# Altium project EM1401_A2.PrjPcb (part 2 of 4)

## Sheet BOTTOM_ACB_Converter.SchDoc: Bottom Tigon (PWM controller)
size B; Date: Not shown in title block; ApprovedBy: Not shown in title block; CheckedBy: Not shown in title block; Author: Not shown in title block; CompanyName: Not shown in title block; DrawnBy: Not shown in title block; Engineer: Not shown in title block; Organization: Not shown in title block; Address1: Not shown in title block; Address2: Not shown in title block; Address3: Not shown in title block; Address4: Not shown in title block; DocumentNumber: 6; Revision: Use project parameter SCH_Rev; SheetNumber: 7; SheetTotal: 14; PageSetup: Record=PageOptions|CenterHorizontal=True|CenterVertical=True|PrintScale=1.09|XCorrection=1.00|YCorrection=1.00|PrintKind=0|BorderSize=5000000|LeftOffset=0|BottomOffset=0|Orientation=2|PaperLength=1000|PaperWidth=1000|Scale=100|PaperSource=15|PrintQuality=600|MediaType=1|DitherType=10|PaperKind=11x17|PrintScaleMode=1
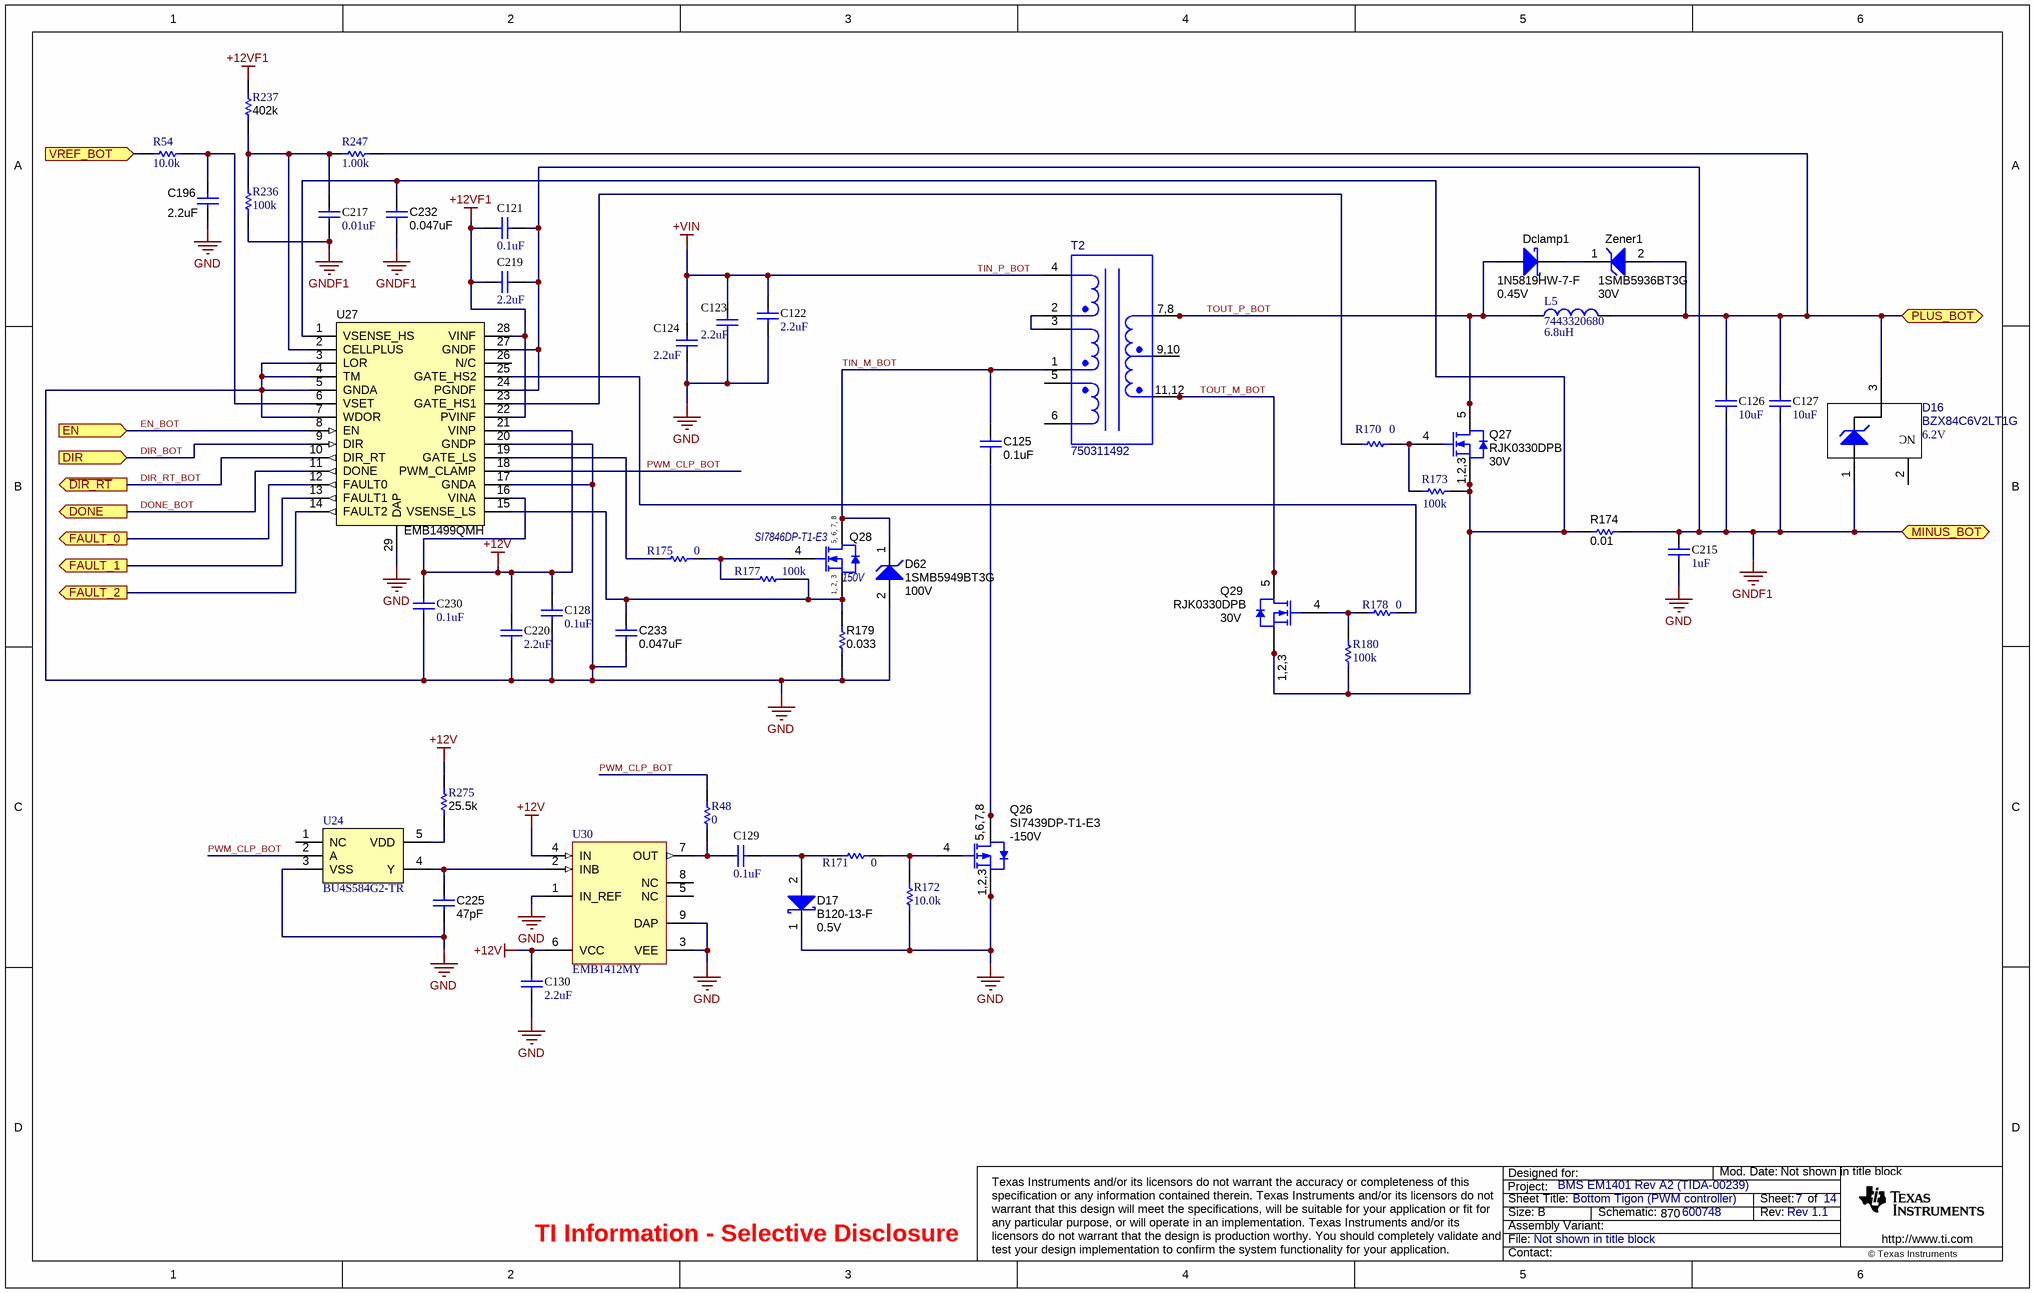
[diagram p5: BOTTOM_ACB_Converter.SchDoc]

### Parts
C121  value 0.1uF  [0603L]  (hidden comment: C1608X7R1C104K)
C122  value 2.2uF  [1210L]  (hidden comment: GRM32ER72A225KA35L)
C123  value 2.2uF  [1210L]  (hidden comment: GRM32ER72A225KA35L)
C124  value 2.2uF  [1210L]  (hidden comment: GRM32ER72A225KA35L)
C125  value 0.1uF  [1206L]  (hidden comment: 12061C104KAT2A)
C126  value 10uF  [1206L]  (hidden comment: GRM319R61A106KE19D)
C127  value 10uF  [1206L]  (hidden comment: GRM319R61A106KE19D)
C128  value 0.1uF  [0603L]  (hidden comment: C1608X7R1C104K)
C129  value 0.1uF  [0603L]  (hidden comment: C1608X7R1C104K)
C130  value 2.2uF  [0805_HV]  (hidden comment: C0805C225K4RACTU)
C196  value 2.2uF  [0603L]  (hidden comment: C1608X5R0J225M)
C215  value 1uF  [1210L]  (hidden comment: GRM32ER72A105KA01L)
C217  value 0.01uF  [0603L]  (hidden comment: GRM188R71C103KA01D)
C219  value 2.2uF  [0805_HV]  (hidden comment: C0805C225K4RACTU)
C220  value 2.2uF  [0805_HV]  (hidden comment: C0805C225K4RACTU)
C225  value 47pF  [0603L]  (hidden comment: 06035A470JAT2A)
C230  value 0.1uF  [0603L]  (hidden comment: C1608X7R1C104K)
C232  value 0.047uF  [0603L]  (hidden comment: C1608X7R1E473K)
C233  value 0.047uF  [0603L]  (hidden comment: C1608X7R1E473K)
D16  BZX84C6V2LT1G  value 6.2V  [MF03A_L]
D17  B120-13-F  value 0.5V  [SMA]
D62  1SMB5949BT3G  value 100V  [SMB]
Dclamp1  1N5819HW-7-F  value 0.45V  [SOD-123]
L5  7443320680  Ind_H: 6.8uH  [Wurth 7443320680]
Q26  SI7439DP-T1-E3  value -150V  [PowerPAK_SO-8]
Q27  RJK0330DPB  value 30V  [LFPAK]
Q28  SI7846DP-T1-E3  value 150V  [PowerPAK_SO-8]
Q29  RJK0330DPB  value 30V  [LFPAK]
R48  value 0  [0603L]  (hidden comment: CRCW06030000Z0EA)
R54  value 10.0k  [0603L]  (hidden comment: RT0603BRD0710KL)
R170  value 0  [0603L]  (hidden comment: CRCW06030000Z0EA)
R171  value 0  [0603L]  (hidden comment: CRCW06030000Z0EA)
R172  value 10.0k  [0603L]  (hidden comment: RT0603BRD0710KL)
R173  value 100k  [0603L]  (hidden comment: CRCW0603100KFKEA)
R174  value 0.01  [2010M]  (hidden comment: WSL2010R0100FEA18)
R175  value 0  [0603L]  (hidden comment: CRCW06030000Z0EA)
R177  value 100k  [0603L]  (hidden comment: CRCW0603100KFKEA)
R178  value 0  [0603L]  (hidden comment: CRCW06030000Z0EA)
R179  value 0.033  [1812]  (hidden comment: ERJ-L12KF33MU)
R180  value 100k  [0603L]  (hidden comment: CRCW0603100KFKEA)
R236  value 100k  [0603L]  (hidden comment: CRCW0603100KFKEA)
R237  value 402k  [0603L]  (hidden comment: RC0603FR-07402KL)
R247  value 1.00k  [0603L]  (hidden comment: CRCW06031K00FKEA)
R275  value 25.5k  [0603L]  (hidden comment: CRCW060325K5FKEA)
T2  750311492  [WE EFD20-SMD Transformer]
U24  BU4S584G2-TR  [MF05A_M]
U27  EMB1499QMH  [MXA28A_M]
U30  EMB1412MY  [MUY08A_N]
Zener1  1SMB5936BT3G  value 30V  [SMB]

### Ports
DIR (in), DONE (out), EN (in), FAULT_0 (out), FAULT_1 (out), FAULT_2 (out), MINUS_BOT (bidir), PLUS_BOT (bidir), VREF_BOT (in), ~{DIR_RT} (out)

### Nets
+12V: C128.2 C130.1 C220.1 C230.2 R275.2 U27.16(VINA) U27.21(VINP) U30.4(IN) U30.6(VCC)
+12VF1: C121.1 C219.1 R237.2 U27.22(PVINF) U27.28(VINF)
GND: C122.2 C123.2 C124.2 C128.1 C130.2 C196.2 C215.2 C220.2 C225.2 C230.1 C233.2 D17.1(K) D62.2(A) Q26.1(S) Q26.2(S) Q26.3(S) R172.2 R179.1 U24.3(VSS) U27.3(LOR) U27.4(TM) U27.5(GNDA) U27.7(WDOR) U27.17(GNDA) U27.20(GNDP) U27.29(DAP) U30.1(IN_REF) U30.3(VEE) U30.9(DAP)  [project net BAT0]
GNDF1: C121.2 C126.2 C127.2 C215.1 C217.2 C219.2 C232.1 D16.1(A) R174.2 R236.2 U27.24(PGNDF) U27.27(GNDF) ; port MINUS_BOT
TIN_P_BOT: C122.1 C123.1 C124.1 T2.4  [also labelled +VIN]
DIR_BOT: U27.9(DIR) ; port DIR
DIR_RT_BOT: U27.10(DIR_RT) ; port ~{DIR_RT}
DONE_BOT: U27.11(DONE) ; port DONE
EN_BOT: U27.8(EN) ; port EN
PWM_CLP_BOT: R48.1 U24.2(A) U27.18(PWM_CLAMP)
TIN_M_BOT: C125.1 D62.1(K) Q28.5(D) Q28.6(D) Q28.7(D) Q28.8(D) T2.1
TOUT_M_BOT: Q29.5(D) Q29.6(D) T2.11 T2.12
TOUT_P_BOT: Dclamp1.2(A) L5.1 Q27.5(D) Q27.6(D) T2.7 T2.8
VREF_BOT_: R54.2 ; port VREF_BOT
NetC125_2: C125.2 Q26.5(D) Q26.6(D) Q26.7(D) Q26.8(D) Q26.9(D)
NetC126_1: C126.1 C127.1 D16.3(K) L5.2 R247.1 Zener1.2(A) ; port PLUS_BOT
NetC129_1: C129.1 D17.2(A) R171.2
NetC129_2: C129.2 R48.2 U30.7(OUT)
NetC196_1: C196.1 R54.1 U27.6(VSET)
NetC217_1: C217.1 R236.1 R237.1 R247.2 U27.2(CELLPLUS)
NetC225_1: C225.1 U24.4(Y) U30.2(INB)
NetC232_2: C232.2 Q27.1(S) Q27.2(S) Q27.3(S) Q29.1(S) Q29.2(S) Q29.3(S) R173.1 R174.1 R180.2 U27.1(VSENSE_HS)
NetC233_1: C233.1 Q28.1(S) Q28.2(S) Q28.3(S) R177.1 R179.2 U27.15(VSENSE_LS)
NetDclamp1_1: Dclamp1.1(K) Zener1.1(K)
NetQ26_4: Q26.4(G) R171.1 R172.1
NetQ27_4: Q27.4(G) R170.1 R173.2
NetQ28_4: Q28.4(G) R175.1 R177.2
NetQ29_4: Q29.4(G) R178.2 R180.1
NetR170_2: R170.2 U27.23(GATE_HS1)
NetR175_2: R175.2 U27.19(GATE_LS)
NetR178_1: R178.1 U27.25(GATE_HS2)
NetR275_1: R275.1 U24.5(VDD)
NetT2_2: T2.2 T2.3
NetT2_9: T2.9 T2.10
NetU6_20: U27.14(FAULT2) ; port FAULT_2
NetU6_21: U27.13(FAULT1) ; port FAULT_1
NetU6_22: U27.12(FAULT0) ; port FAULT_0

Not connected (* = marked no-connect by the designer): D16 2(NC); T2 5 6; U24 1(NC); U27 26(N/C); U30 5(NC) 8(NC)

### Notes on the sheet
- TI Information - Selective Disclosure

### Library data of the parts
C121 C128 C129 C230 = C1608X7R1C104K: CAP, CERM, 0.1uF, 16V, +/-10%, X7R, 0603; Manufacturer: TDK; Cap_Case: 0603; ESR_Ohm: 0.017; Polarized: N; TaMax_C: 125; TaMin_C: -55; Tolerance_%: 10; VDC_V: 16; Cap_F: 0.0000001; CompType: Capacitor; Value1: 0.017 ohm; U/M: EA; ValueDisplayed: 0.1µF
C122-C124 = GRM32ER72A225KA35L: CAP, CERM, 2.2uF, 100V, +/-10%, X7R, 1210; Manufacturer: MuRata; Cap_Case: 1210; ESR_Ohm: 0.007; IRMS_A: 4.4; Polarized: N; TaMax_C: 125; TaMin_C: -55; Tolerance_%: 10; VDC_V: 100; Cap_F: 0.0000022; CompType: Capacitor; Value1: 0.007 ohm; U/M: EA; ValueDisplayed: 2.2µF
C125 = 12061C104KAT2A: CAP, CERM, 0.1uF, 100V, +/-10%, X7R, 1206; Manufacturer: AVX; Cap_Case: 1206; ESR_Ohm: 0.037; Polarized: N; TaMax_C: 125; TaMin_C: -55; Tolerance_%: 10; VDC_V: 100; Cap_F: 0.0000001; CompType: Capacitor; Value1: 0.037 ohm; U/M: EA; ValueDisplayed: 0.1µF
C126 C127 = GRM319R61A106KE19D: CAP, CERM, 10uF, 10V, +/-10%, X5R, 1206; Manufacturer: MuRata; Cap_Case: 1206; ESR_Ohm: 0.004; Polarized: N; TaMax_C: 85; TaMin_C: -55; Tolerance_%: 10; Cap_F: 0.00001; CompType: Capacitor; Value1: 0.004 ohm; U/M: EA; ValueDisplayed: 10µF
C130 C219 C220 = C0805C225K4RACTU: CAP, CERM, 2.2uF, 16V, +/-10%, X7R, 0805; Manufacturer: Kemet; Cap_Case: 0805; ESR_Ohm: 0.008; IRMS_A: 15.55; Polarized: N; TaMax_C: 125; TaMin_C: -55; Tolerance_%: 10; VDC_V: 16; Cap_F: 0.0000022; CompType: Capacitor; Value1: 0.008 ohm; U/M: EA; ValueDisplayed: 2.2µF
C196 = C1608X5R0J225M: CAP, CERM, 2.2uF, 6.3V, +/-20%, X5R, 0603; Manufacturer: TDK; Cap_Case: 0603; ESR_Ohm: 0.004; Polarized: N; TaMax_C: 85; TaMin_C: -55; Tolerance_%: 20; VDC_V: 6.3; Cap_F: 0.0000022; CompType: Capacitor; Value1: 0.004 ohm; U/M: EA; ValueDisplayed: 2.2µF
C215 = GRM32ER72A105KA01L: CAP, CERM, 1uF, 100V, +/-10%, X7R, 1210; Manufacturer: MuRata; Cap_Case: 1210; Polarized: N; TaMax_C: 125; TaMin_C: -55; Tolerance_%: 10; VDC_V: 100; Cap_F: 0.000001; CompType: Capacitor; U/M: EA; ValueDisplayed: 1µF
C217 = GRM188R71C103KA01D: CAP, CERM, 0.01uF, 16V, +/-10%, X7R, 0603; Manufacturer: MuRata; Cap_Case: 0603; Polarized: N; TaMax_C: 125; TaMin_C: -55; Tolerance_%: 10; VDC_V: 16; Cap_F: 0.00000001; CompType: Capacitor; U/M: EA; ValueDisplayed: 0.01µF
C225 = 06035A470JAT2A: CAP, CERM, 47pF, 50V, +/-5%, C0G/NP0, 0603; Manufacturer: AVX; Cap_Case: 0603; ESR_Ohm: 0.174; Polarized: N; TaMax_C: 125; TaMin_C: -55; Tolerance_%: 5; VDC_V: 50; Cap_F: 0.000000000047; CompType: Capacitor; Value1: 0.174 ohm; U/M: EA
C232 C233 = C1608X7R1E473K: CAP, CERM, 0.047uF, 25V, +/-10%, X7R, 0603; Manufacturer: TDK; Cap_Case: 0603; ESR_Ohm: 0.0234; Polarized: N; TaMax_C: 125; TaMin_C: -55; Tolerance_%: 10; VDC_V: 25; Cap_F: 0.000000047; CompType: Capacitor; Value1: 0.0234 ohm; U/M: EA; ValueDisplayed: 0.047µF
D16 = BZX84C6V2LT1G: SMT Zener Diode; Manufacturer: ON Semiconductor; Power_W: 0.225; Vz: 6.2; Value1: 0.225V; RJA_CperW: 556
D17 = B120-13-F: Diode, Schottky, 20V, 1A, SMA; Manufacturer: Diodes Inc.; RJC_CperW: 20; Vf_V: 0.5; Io_A: 1; TJMax_C: 150; U/M: EA
D62 = 1SMB5949BT3G: Diode, Zener, 100V, 550mW, SMB; Manufacturer: ON Semiconductor; U/M: EA; Power_W: 0.55; Vz: 100; Value1: 0.55W; RJA_CperW: 226
Dclamp1 = 1N5819HW-7-F: Diode, Schottky, 40V, 1A, SOD-123; Manufacturer: Diodes Inc.; Vf_V: 0.45; Io_A: 1; Vr_V: 40; TJMax_C: 125; U/M: EA
L5 = 7443320680: Wurth 6.8uH Power Inductor; Manufacturer: Wurth Elektronik; DCR_Ohm: 8.98; Value1: 13A
Q26 = SI7439DP-T1-E3: MOSFET, P-CH, -150V, -3A, PowerPAK SO-8; Manufacturer: Vishay-Siliconix; ChType: P; VdsMax_V: -150; Value1: ? ohm; Value2: 88 nC; QgTyp_nC: 88; Vgs_V: -20; IdsMax_A: -3; U/M: EA
Q27 Q29 = RJK0330DPB: 45A, 27nC, rDS(on) @ 4.5V =0.0028 ohm; Manufacturer: Renesas; CompType: MOSFET; ChType: N; VdsMax_V: 30; Rdson45_Ohm: 0.0028; QgTyp_nC: 27; Vgs_V: 20; IdsMax_A: 45
Q28 = BSC014N03LS G: 100A, 47nC, rDS(on) @ 4.5V =0.0021 Ohm; Manufacturer: Vishay/Siliconix; DesignatorOriginal: Q1-tw; A_Properties: MOSFET N-CH 150V 4A PPAK 8SOIC; Type: N-CH FET; Value1: 50mOhm; Value2: 30nC
R48 R170 R171 R175 R178 = CRCW06030000Z0EA: RES, 0 ohm, 5%, 0.1W, 0603; Manufacturer: Vishay-Dale; CompType: Resistor; Tolerance_%: 5; VDC_V: 75; Power_W: 0.1; Value_Code: 0000; EIA_Code: E24; TempCo: 200 ppm/C; U/M: EA
R54 R172 = RT0603BRD0710KL: RES, 10.0k ohm, 0.1%, 0.1W, 0603; Manufacturer: Yageo America; CompType: Resistor; Tolerance_%: 0.1; VDC_V: 75; Res_Ohm: 10000; Value_Code: 10k0; EIA_Code: E192; TempCo: 25 ppm/C; U/M: EA
R173 R177 R180 R236 = CRCW0603100kFKEA: RES, 100k ohm, 1%, 0.1W, 0603; Manufacturer: Vishay-Dale; CompType: Resistor; Tolerance_%: 1; VDC_V: 75; Power_W: 0.1; Res_Ohm: 100000; EIA_Code: E96; TempCo: 100 ppm/C; U/M: EA
R174 = WSL2010R0100FEA18: RES, 0.01 ohm, 1%, 1W, 2010; Manufacturer: Vishay-Dale; CompType: Resistor; Tolerance_%: 1; Value_Code: R010; EIA_Code: E96; TempCo: 75 ppm/C; U/M: EA
R179 = ERJ-L12KF33MU: RES, 0.033 ohm, 1%, 0.5W, 1812; Manufacturer: Panasonic; CompType: Resistor; Tolerance_%: 1; Power_W: 0.5; Value_Code: R033; EIA_Code: E96; TempCo: 300 ppm/C; U/M: EA
R237 = RC0603FR-07402KL: RES, 402k ohm, 1%, 0.1W, 0603; Manufacturer: Yageo America; CompType: Resistor; Tolerance_%: 1; VDC_V: 150; Power_W: 0.1; Res_ohm: 402000; EIA_Code: E96; U/M: EA; TempCo: 200 ppm/C
R247 = CRCW06031k00FKEA: RES, 1.00k ohm, 1%, 0.1W, 0603; Manufacturer: Vishay-Dale; CompType: Resistor; Tolerance_%: 1; VDC_V: 75; Power_W: 0.1; Res_Ohm: 1000; Value_Code: 1k00; EIA_Code: E96; TempCo: 100 ppm/C; U/M: EA
R275 = CRCW060325K5FKEA: RES, 25.5k ohm, 1%, 0.1W, 0603; Manufacturer: Vishay-Dale; CompType: Resistor; Tolerance_%: 1; VDC_V: 75; Power_W: 0.1; Res_Ohm: 25500; Value_Code: 25k5; EIA_Code: E96; TempCo: 100 ppm/C; U/M: EA
T2 = EFD20-SMD: Forward Transformer; Manufacturer: Wurth Elektronik; SymbolVersion: use current date i.e. 2008-05-20; SymbolCreator: Use LDAP id
U24 = BU4S584G2-TR: IC INVERTER WITH SCHMITT TRIGGER SINGLE; Manufacturer: Rohm Semiconductor; Res_Ohm: 200000; Value1: 3V-16V; Value2: 3.4mA Drive
U27 = EMB1499QMH: PWM Controller; Manufacturer: National Semiconductor; CompType: Used in BOM report; SymbolVersion: use current date i.e. 2008-05-20; SymbolCreator: Use LDAP id
U30 = EMB1412MY: Dual 5A Compound Gate Driver; Manufacturer: National Semiconductor; CompType: Switcher; PowerWise: N
Zener1 = 1SMB5936BT3G: Diode, Zener, 30V, 550mW, SMB; Manufacturer: ON Semiconductor; U/M: EA; Power_W: 0.55; Vz: 30; Value1: 0.55W; RJA_CperW: 226

## Sheet VR.SchDoc: VR (Power Supplies)
size B; Date: Not shown in title block; ApprovedBy: Not shown in title block; CheckedBy: Not shown in title block; Author: Not shown in title block; CompanyName: Not shown in title block; DrawnBy: Not shown in title block; Engineer: Not shown in title block; Organization: Not shown in title block; Address1: Not shown in title block; Address2: Not shown in title block; Address3: Not shown in title block; Address4: Not shown in title block; DocumentNumber: 15; Revision: Use project parameter SCH_Rev; SheetNumber: 13; SheetTotal: 14; PageSetup: Record=PageOptions|CenterHorizontal=True|CenterVertical=True|PrintScale=0.70|XCorrection=1.00|YCorrection=1.00|PrintKind=0|BorderSize=5000000|LeftOffset=0|BottomOffset=0|Orientation=2|PaperLength=1000|PaperWidth=1000|Scale=100|PaperSource=268|PrintQuality=-3|MediaType=1|DitherType=10|PaperKind=Letter 8.5"x11"|PrintScaleMode=1
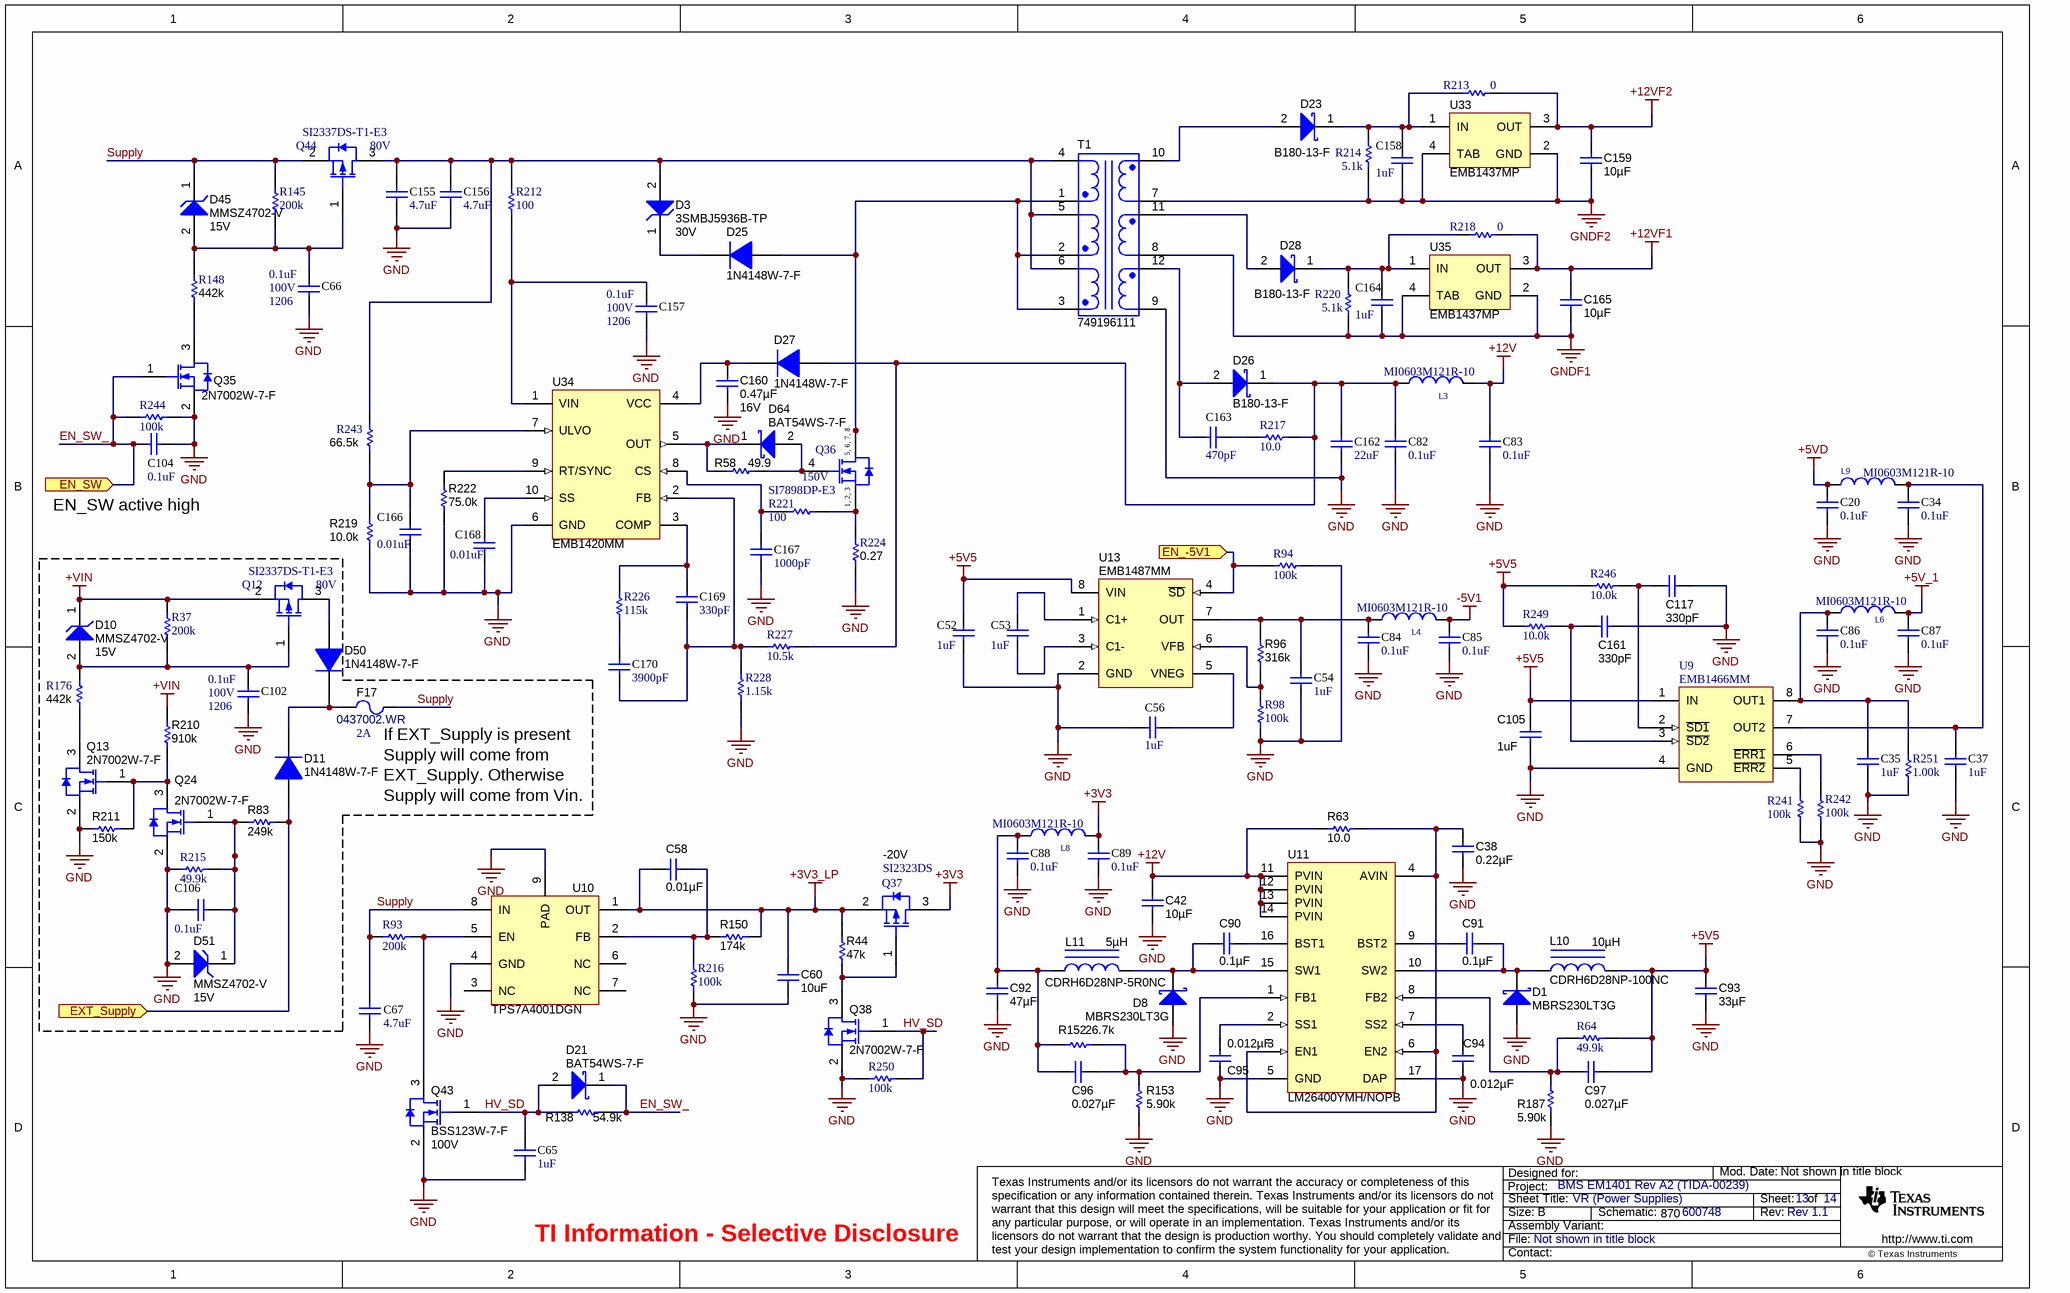
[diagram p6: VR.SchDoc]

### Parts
C20  value 0.1uF  [0603L]  (hidden comment: C1608X7R1C104K)
C34  value 0.1uF  [0603L]  (hidden comment: C1608X7R1C104K)
C35  value 1uF  [0805_HV]  (hidden comment: C2012X7R1E105K)
C37  value 1uF  [0805_HV]  (hidden comment: C2012X7R1E105K)
C38  ValueDisplayed: 0.22µF  [0603L]  (hidden comment: C1608X7R1C224K)
C42  ValueDisplayed: 10µF  [1210]  (hidden comment: GRM32DR61E106KA12L)
C52  value 1uF  [0805_HV]  (hidden comment: C2012X7R1E105K)
C53  value 1uF  [0805_HV]  (hidden comment: C2012X7R1E105K)
C54  value 1uF  [0805_HV]  (hidden comment: C2012X7R1E105K)
C56  value 1uF  [0805_HV]  (hidden comment: C2012X7R1E105K)
C58  ValueDisplayed: 0.01µF  [0805_HV]  (hidden comment: GRM21BR72A103KA01L)
C60  value 10uF  [1206L]  (hidden comment: C3216X7R1C106M)
C65  value 1uF  [0805_HV]  (hidden comment: C2012X7R1E105K)
C66  value 0.1uF  PackageReference: 1206  Value2: 100V  [1206L]  (hidden comment: C3216X7R2A104K)
C67  value 4.7uF  [1210L]  (hidden comment: GRM32ER71H475KA88L)
C82  value 0.1uF  [0603L]  (hidden comment: C1608X7R1C104K)
C83  value 0.1uF  [0603L]  (hidden comment: C1608X7R1C104K)
C84  value 0.1uF  [0603L]  (hidden comment: C1608X7R1C104K)
C85  value 0.1uF  [0603L]  (hidden comment: C1608X7R1C104K)
C86  value 0.1uF  [0603L]  (hidden comment: C1608X7R1C104K)
C87  value 0.1uF  [0603L]  (hidden comment: C1608X7R1C104K)
C88  value 0.1uF  [0603L]  (hidden comment: C1608X7R1C104K)
C89  value 0.1uF  [0603L]  (hidden comment: C1608X7R1C104K)
C90  ValueDisplayed: 0.1µF  [0603L]  (hidden comment: C1608X7R1C104K)
C91  ValueDisplayed: 0.1µF  [0603L]  (hidden comment: C1608X7R1C104K)
C92  ValueDisplayed: 47µF  [0805_HV]  (hidden comment: JMK212BJ476MG-T)
C93  ValueDisplayed: 33µF  [1210]  (hidden comment: GRM32DR60J336ME19L)
C94  ValueDisplayed: 0.012µF  [0603L]  (hidden comment: GRM188R71C123KA01D)
C95  ValueDisplayed: 0.012µF  [0603L]  (hidden comment: GRM188R71C123KA01D)
C96  ValueDisplayed: 0.027µF  [0603L]  (hidden comment: GRM188R71E273KA01D)
C97  ValueDisplayed: 0.027µF  [0603L]  (hidden comment: GRM188R71E273KA01D)
C102  value 0.1uF  PackageReference: 1206  Value2: 100V  [1206L]  (hidden comment: C3216X7R2A104K)
C104  value 0.1uF  [0603L]  (hidden comment: C1608X7R1C104K)
C105  value 1uF  [0603L]  (hidden comment: C1608X7R1C105K)
C106  value 0.1uF  [0603L]  (hidden comment: C1608X7R1C104K)
C117  ValueDisplayed: 330pF  [0603L]  (hidden comment: C0603C331K5RACTU)
C155  value 4.7uF  [1210L]  (hidden comment: GRM32ER71H475KA88L)
C156  value 4.7uF  [1210L]  (hidden comment: GRM32ER71H475KA88L)
C157  value 0.1uF  PackageReference: 1206  Value2: 100V  [1206L]  (hidden comment: C3216X7R2A104K)
C158  value 1uF  [0805_HV]  (hidden comment: C2012X7R1E105K)
C159  ValueDisplayed: 10µF  [1210]  (hidden comment: C3225X7R1C106M)
C160  ValueDisplayed: 0.47µF  Value2: 16V  [0603]  (hidden comment: GRM188R61C474KA93D)
C161  ValueDisplayed: 330pF  [0603L]  (hidden comment: C0603C331K5RACTU)
C162  value 22uF  [1210L]  (hidden comment: C3225X5R1C226M)
C163  value 470pF  [0805_HV]  (hidden comment: CC0805JRNP09BN471)
C164  value 1uF  [0805_HV]  (hidden comment: C2012X7R1E105K)
C165  ValueDisplayed: 10µF  [1210]  (hidden comment: C3225X7R1C106M)
C166  value 0.01uF  [0603L]  (hidden comment: GRM188R71E103KA01D)
C167  value 1000pF  [0603L]  (hidden comment: 06035A102KAT2A)
C168  value 0.01uF  [0603L]  (hidden comment: GRM188R71E103KA01D)
C169  value 330pF  [0603L]  (hidden comment: 06035A331JAT2A)
C170  value 3900pF  [0603L]  (hidden comment: GRM188R71H392KA01D)
D1  MBRS230LT3G  [SMB]
D3  3SMBJ5936B-TP  value 30V  [SMB]
D8  MBRS230LT3G  [SMB]
D10  MMSZ4702-V  value 15V  [SOD-123]
D11  1N4148W-7-F  [SOD-123]
D21  BAT54WS-7-F  [sod-323]
D23  B180-13-F  [SMA]
D25  1N4148W-7-F  [SOD-123]
D26  B180-13-F  [SMA]
D27  1N4148W-7-F  [SOD-123]
D28  B180-13-F  [SMA]
D45  MMSZ4702-V  value 15V  [SOD-123]
D50  1N4148W-7-F  [SOD-123]
D51  MMSZ4702-V  value 15V  [SOD-123]
D64  BAT54WS-7-F  [sod-323]
F17  0437002.WR  value 2A  [1206M]
L3  MI0603M121R-10  [0603]
L4  MI0603M121R-10  [0603]
L6  MI0603M121R-10  [0603]
L8  MI0603M121R-10  [0603]
L9  MI0603M121R-10  [0603]
L10  CDRH6D28NP-100NC  ValueDisplayed: 10µH  [CDRH6D28]
L11  CDRH6D28NP-5R0NC  ValueDisplayed: 5µH  [CDRH6D28]
Q12  SI2337DS-T1-E3  value 80V  [MF03A_N]
Q13  2N7002W-7-F  [SOT-323]
Q24  2N7002W-7-F  [SOT-323]
Q35  2N7002W-7-F  [SOT-323]
Q36  SI7898DP-E3  value 150V  [PowerPAK_SO-8]
Q37  SI2323DS  value -20V  [SOT-23]
Q38  2N7002W-7-F  [SOT-323]
Q43  BSS123W-7-F  value 100V  [SOT-323]
Q44  SI2337DS-T1-E3  value 80V  [MF03A_N]
R37  value 200k  [0603L]  (hidden comment: CRCW0603200KJNEA)
R44  value 47k  [0603L]  (hidden comment: CRCW060347K0JNEA)
R58  value 49.9  [0603L]  (hidden comment: CRCW060349R9FKEA)
R63  value 10.0  [0603L]  (hidden comment: CRCW060310R0FKEA)
R64  value 49.9k  [0603L]  (hidden comment: CRCW060349K9FKEA)
R83  value 249k  [0603L]  (hidden comment: CRCW0603249KFKEA)
R93  value 200k  [0603L]  (hidden comment: CRCW0603200KJNEA)
R94  value 100k  [0603L]  (hidden comment: RT0603DRE07100KL)
R96  value 316k  [0603L]  (hidden comment: CRCW0603316KFKEA)
R98  value 100k  [0603L]  (hidden comment: RT0603DRE07100KL)
R138  value 54.9k  [0603L]  (hidden comment: CRCW060354K9FKEA)
R145  value 200k  [0603L]  (hidden comment: CRCW0603200KJNEA)
R148  value 442k  [0603L]  (hidden comment: CRCW0603442KFKEA)
R150  value 174k  [0603L]  (hidden comment: CRCW0603174KFKEA)
R152  value 26.7k  [0603L]  (hidden comment: CRCW060326K7FKEA)
R153  value 5.90k  [0603L]  (hidden comment: CRCW06035K90FKEA)
R176  value 442k  [0603L]  (hidden comment: CRCW0603442KFKEA)
R187  value 5.90k  [0603L]  (hidden comment: CRCW06035K90FKEA)
R210  value 910k  [0603L]  (hidden comment: CRCW0603910KJNEA)
R211  value 150k  [0603L]  (hidden comment: CRCW0603150KJNEA)
R212  value 100  [1206L]  (hidden comment: CRCW1206100RFKEA)
R213  value 0  [0603L]  (hidden comment: CRCW06030000Z0EA)
R214  value 5.1k  [0805_HV]  (hidden comment: CRCW08055K10JNEA)
R215  value 49.9k  [0603L]  (hidden comment: CRCW060349K9FKEA)
R216  value 100k  [0603L]  (hidden comment: RT0603DRE07100KL)
R217  value 10.0  [1206L]  (hidden comment: CRCW120610R0FKEA)
R218  value 0  [0603L]  (hidden comment: CRCW06030000Z0EA)
R219  value 10.0k  [0603L]  (hidden comment: CRCW060310K0FKEA)
R220  value 5.1k  [0805_HV]  (hidden comment: CRCW08055K10JNEA)
R221  value 100  [0603L]  (hidden comment: CRCW0603100RFKEA)
R222  value 75.0k  [0603L]  (hidden comment: CRCW060375K0FKEA)
R224  value 0.27  [1210M]  (hidden comment: MCR25JZHFLR270)
R226  value 115k  [0603L]  (hidden comment: CRCW0603115KFKEA)
R227  value 10.5k  [0603L]  (hidden comment: CRCW060310K5FKEA)
R228  value 1.15k  [0603L]  (hidden comment: CRCW06031K15FKEA)
R241  value 100k  [0603L]  (hidden comment: RT0603DRE07100KL)
R242  value 100k  [0603L]  (hidden comment: RT0603DRE07100KL)
R243  value 66.5k  [0603L]  (hidden comment: CRCW060366K5FKEA)
R244  value 100k  [0603L]  (hidden comment: RT0603DRE07100KL)
R246  value 10.0k  [0603L]  (hidden comment: CRCW060310K0FKEA)
R249  value 10.0k  [0603L]  (hidden comment: CRCW060310K0FKEA)
R250  value 100k  [0603L]  (hidden comment: RT0603DRE07100KL)
R251  value 1.00k  [0603L]  (hidden comment: CRCW06031K00FKEA)
T1  749196111  [749196111]
U9  EMB1466MM  [MUA08A_N]
U10  TPS7A4001DGN  [MUY08A_N]
U11  LM26400YMH/NOPB  [MXA16A_N]
U13  EMB1487MM  [MUA08A_N]
U33  EMB1437MP  [MP04A_N]
U34  EMB1420MM  [MUB10A_N]
U35  EMB1437MP  [MP04A_N]

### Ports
EN_-5V1 (in), EN_SW (in), EXT_Supply (in)

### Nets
+3V3: C89.2 L8.2 Q37.3(D)
+3V3_LP: C58.1 C60.1 Q37.2(S) R44.1 R150.2 U10.1(OUT)
+5V5: C52.1 C93.1 C97.1 C105.1 L10.2 R64.1 R246.2 R249.2 U9.1(IN) U13.8(VIN)
+5V_1: C87.2 L6.2
+5VD: C20.2 L9.1
+12V: C42.1 C83.2 L3.2 R63.1 U11.11(PVIN) U11.12(PVIN) U11.13(PVIN) U11.14(PVIN)
+12VF1: C165.1 R218.2 U35.3(OUT)
+12VF2: C159.1 R213.2 U33.3(OUT)
+VIN: D10.1(K) Q12.2(S) R37.2 R210.2  [project net TIN_P_BOT]
-5V1: C85.2 L4.2
GND: C20.1 C34.1 C35.2 C37.2 C38.1 C42.2 C52.2 C54.1 C56.1 C60.2 C65.1 C66.1 C67.2 C82.1 C83.1 C84.1 C85.1 C86.1 C87.1 C88.1 C89.1 C92.2 C93.2 C94.1 C95.1 C102.1 C104.1 C105.2 C106.2 C117.1 C155.2 C156.2 C157.1 C160.1 C161.1 C162.2 C166.1 C167.2 C168.1 D1.2(K) D8.2(K) D51.2(A) Q13.2(S) Q24.2(S) Q35.2(S) Q38.2(S) Q43.2(S) R94.1 R98.2 R153.1 R187.1 R211.2 R215.2 R216.2 R219.1 R222.1 R224.1 R228.1 R241.2 R242.2 R244.2 R250.1 R251.2 T1.9 U9.4(GND) U10.4(GND) U10.9(PAD) U11.5(GND) U11.17(DAP) U13.2(GND) U34.6(GND)  [project net BAT0]
GNDF1: C164.2 C165.2 R220.1 T1.8 U35.2(GND) U35.4(TAB)
GNDF2: C158.2 C159.2 R214.1 T1.7 U33.2(GND) U33.4(TAB)
EN_SW_: C104.2 D21.1(K) Q35.1(G) R138.2 R244.1 ; port EN_SW
HV_SD: C65.2 D21.2(A) Q38.1(G) Q43.1(G) R138.1 R250.2
Supply: C67.1 D45.1(K) F17.1 Q44.2(S) R93.1 R145.2 U10.8(IN)
NetC34_2: C34.2 C37.1 L9.2 U9.7(OUT2)
NetC35_1: C35.1 C86.2 L6.1 R251.1 U9.8(OUT1)
NetC38_2: C38.2 R63.2 U11.3(EN1) U11.4(AVIN) U11.6(EN2)
NetC53_1: C53.1 U13.1(C1+)
NetC53_2: C53.2 U13.3(C1-)
NetC54_2: C54.2 C84.2 L4.1 R96.2 U13.7(OUT)
NetC56_2: C56.2 U13.5(VNEG)
NetC58_2: C58.2 R150.1 R216.1 U10.2(FB)
NetC66_2: C66.2 D45.2(A) Q44.1(G) R145.1 R148.2
NetC82_2: C82.2 C162.1 D26.1(K) D27.2(A) L3.1 R217.1 R227.2
NetC88_2: C88.2 C92.1 C96.2 L8.1 L11.1 R152.1
NetC90_1: C90.1 U11.16(BST1)
NetC90_2: C90.2 D8.1(A) L11.2 U11.15(SW1)
NetC91_1: C91.1 D1.1(A) L10.1 U11.10(SW2)
NetC91_2: C91.2 U11.9(BST2)
NetC94_2: C94.2 U11.7(SS2)
NetC95_2: C95.2 U11.2(SS1)
NetC96_1: C96.1 R152.2 R153.2 U11.1(FB1)
NetC97_2: C97.2 R64.2 R187.2 U11.8(FB2)
NetC102_2: C102.2 D10.2(A) Q12.1(G) R37.1 R176.2
NetC106_1: C106.1 D51.1(K) Q24.1(G) R83.1 R215.1
NetC117_2: C117.2 R246.1 U9.2(~{SD1})
NetC155_1: C155.1 C156.1 D3.2(A) Q44.3(D) R212.1 R243.2 T1.4 T1.5 T1.6
NetC157_2: C157.2 R212.2 U34.1(VIN)
NetC158_1: C158.1 D23.1(K) R213.1 R214.2 U33.1(IN)
NetC160_2: C160.2 D27.1(K) U34.4(VCC)
NetC161_2: C161.2 R249.1 U9.3(~{SD2})
NetC163_1: C163.1 D26.2(A) T1.12
NetC163_2: C163.2 R217.2
NetC164_1: C164.1 D28.1(K) R218.1 R220.2 U35.1(IN)
NetC166_2: C166.2 R219.2 R243.1 U34.7(ULVO)
NetC167_1: C167.1 R221.1 U34.8(CS)
NetC168_2: C168.2 U34.10(SS)
NetC169_1: C169.1 C170.1 R227.1 R228.2 U34.2(FB)
NetC169_2: C169.2 R226.2 U34.3(COMP)
NetC170_2: C170.2 R226.1
NetD3_1: D3.1(K) D25.1(K)
NetD11_1: D11.1(K) D50.1(K) F17.2
NetD11_2: D11.2(A) R83.2 ; port EXT_Supply
NetD23_2: D23.2(A) T1.10
NetD25_2: D25.2(A) Q36.5(D) Q36.6(D) Q36.7(D) Q36.8(D) Q36.9(D) T1.1 T1.2 T1.3
NetD28_2: D28.2(A) T1.11
NetD50_2: D50.2(A) Q12.3(D)
NetD64_1: D64.1(K) R58.1 U34.5(OUT)
NetD64_2: D64.2(A) Q36.4(G) R58.2
NetQ13_1: Q13.1(G) Q24.3(D) R210.1 R211.1
NetQ13_3: Q13.3(D) R176.1
NetQ35_3: Q35.3(D) R148.1
NetQ36_1: Q36.1(S) Q36.2(S) Q36.3(S) R221.2 R224.2
NetQ37_1: Q37.1(G) Q38.3(D) R44.2
NetQ43_3: Q43.3(D) R93.2 U10.5(EN)
NetR94_2: R94.2 U13.4(~{SD}) ; port EN_-5V1
NetR96_1: R96.1 R98.1 U13.6(VFB)
NetR222_2: R222.2 U34.9(RT/SYNC)
NetR241_1: R241.1 U9.5(~{ERR2})
NetR242_1: R242.1 U9.6(~{ERR1})

Not connected (* = marked no-connect by the designer): U10 3(NC) 6(NC) 7(NC)

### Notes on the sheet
- EN_SW active high
- (near F17) If EXT_Supply is present
- (near F17) Supply will come from
- EXT_Supply. Otherwise
- Supply will come from Vin.
- TI Information - Selective Disclosure

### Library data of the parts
C20 C34 C82-C89 C104 C106 = C1608X7R1C104K: as C121 on sheet BOTTOM_ACB_Converter
C35 C37 C52-C54 C56 C65 C158 C164 = C2012X7R1E105K: CAP, CERM, 1uF, 25V, +/-10%, X7R, 0805; Manufacturer: TDK; Cap_Case: 0805; ESR_Ohm: 0.0075; Polarized: N; TaMax_C: 125; TaMin_C: -55; Tolerance_%: 10; VDC_V: 25; Cap_F: 0.000001; CompType: Capacitor; Value1: 0.0075 ohm; U/M: EA; ValueDisplayed: 1µF
C38 = C1608X7R1C224K: CAP, CERM, 0.22uF, 16V, +/-10%, X7R, 0603; Manufacturer: TDK; Cap_Case: 0603; ESR_Ohm: 0.0125; Polarized: N; TaMax_C: 125; TaMin_C: -55; Tolerance_%: 10; VDC_V: 16; Cap_F: 0.00000022; CompType: Capacitor; U/M: EA; Value1: 0.0125 ohm
C42 = GRM32DR61E106KA12L: CAP, CERM, 10uF, 25V, +/-10%, X5R, 1210; Manufacturer: MuRata; Polarized: N; TaMax_C: 85; TaMin_C: -55; Tolerance_%: 10; VDC_V: 25; Cap_F: 0.00001; CompType: Capacitor; U/M: EA
C58 = GRM21BR72A103KA01L: CAP, CERM, 0.01uF, 100V, +/-10%, X7R, 0805; Manufacturer: MuRata; Cap_Case: 0805; Polarized: N; TaMax_C: 125; TaMin_C: -55; Tolerance_%: 10; VDC_V: 100; Cap_F: 0.00000001; CompType: Capacitor; U/M: EA
C60 = C3216X7R1C106M: CAP, CERM, 10uF, 16V, +/-20%, X7R, 1206; Manufacturer: TDK; Cap_Case: 1206; ESR_Ohm: 0.0046; Polarized: N; TaMax_C: 125; TaMin_C: -55; Tolerance_%: 20; VDC_V: 16; Cap_F: 0.00001; CompType: Capacitor; Value1: 0.0046 ohm; U/M: EA; ValueDisplayed: 10µF
C66 C102 C157 = C3216X7R2A104K: CAP, CERM, 0.1uF, 100V, +/-10%, X7R, 1206; Manufacturer: TDK; ESR_Ohm: 0.0259; IRMS_A: 1.5; Polarized: N; TaMax_C: 125; TaMin_C: -55; Tolerance_%: 10; VDC_V: 100; Cap_F: 0.0000001; CompType: Capacitor; Value1: 0.0259 ohm; U/M: EA; ValueDisplayed: 0.1µF
C67 C155 C156 = GRM32ER71H475KA88L: CAP, CERM, 4.7uF, 50V, +/-10%, X7R, 1210; Manufacturer: MuRata; Cap_Case: 1210; ESR_Ohm: 0.002; Polarized: N; TaMax_C: 125; TaMin_C: -55; Tolerance_%: 10; VDC_V: 50; Cap_F: 0.0000047; CompType: Capacitor; Value1: 0.002 ohm; U/M: EA; ValueDisplayed: 4.7µF
C90 C91 = C1608X7R1C104K: CAP, CERM, 0.1uF, 16V, +/-10%, X7R, 0603; Manufacturer: TDK; Cap_Case: 0603; ESR_Ohm: 0.017; Polarized: N; TaMax_C: 125; TaMin_C: -55; Tolerance_%: 10; VDC_V: 16; Cap_F: 0.0000001; CompType: Capacitor; U/M: EA; Value1: 0.017 ohm
C92 = JMK212BJ476MG-T: CAP, CERM, 47uF, 6.3V, +/-20%, X5R, 0805; Manufacturer: Taiyo Yuden; Cap_Case: 0805; Polarized: N; TaMax_C: 85; TaMin_C: -55; Tolerance_%: 20; VDC_V: 6.3; Cap_F: 0.000047; CompType: Capacitor; U/M: EA
C93 = GRM32DR60J336ME19L: CAP, CERM, 33uF, 6.3V, +/-20%, X5R, 1210; Manufacturer: MuRata; ESR_Ohm: 0.006; Polarized: N; TaMax_C: 85; TaMin_C: -55; Tolerance_%: 20; VDC_V: 6.3; Cap_F: 0.000033; CompType: Capacitor; U/M: EA; Value1: 0.006 ohm
C94 C95 = GRM188R71C123KA01D: CAP, CERM, 0.012uF, 16V, +/-10%, X7R, 0603; Manufacturer: MuRata; Cap_Case: 0603; Polarized: N; TaMax_C: 125; TaMin_C: -55; Tolerance_%: 10; VDC_V: 16; Cap_F: 0.000000012; CompType: Capacitor; U/M: EA
C96 C97 = GRM188R71E273KA01D: CAP, CERM, 0.027uF, 25V, +/-10%, X7R, 0603; Manufacturer: MuRata; Cap_Case: 0603; Polarized: N; TaMax_C: 125; TaMin_C: -55; Tolerance_%: 10; VDC_V: 25; Cap_F: 0.000000027; CompType: Capacitor; U/M: EA
C105 = C1608X7R1C105K: CAP, CERM, 1uF, 16V, +/-10%, X7R, 0603; Manufacturer: TDK; Cap_Case: 0603; ESR_Ohm: 0.0057; Polarized: N; TaMax_C: 125; TaMin_C: -55; Tolerance_%: 10; VDC_V: 16; Cap_F: 0.000001; CompType: Capacitor; Value1: 0.0057 ohm; U/M: EA; ValueDisplayed: 1µF
C117 C161 = C0603C331K5RACTU: CAP, CERM, 330pF, 50V, +/-10%, X7R, 0603; Manufacturer: Kemet; Cap_Case: 0603; Polarized: N; TaMax_C: 125; TaMin_C: -55; Tolerance_%: 10; VDC_V: 50; Cap_F: 0.00000000033; CompType: Capacitor; U/M: EA
C159 C165 = C3225X7R1C106M: CAP, CERM, 10uF, 16V, +/-20%, X7R, 1210; Manufacturer: TDK; ESR_Ohm: 0.0027; IRMS_A: 3; Polarized: N; TaMax_C: 125; TaMin_C: -55; Tolerance_%: 20; VDC_V: 16; Cap_F: 0.00001; CompType: Capacitor; Value1: 0.0027 ohm; U/M: EA
C160 = GRM188R61C474KA93D: CAP, CERM, 0.47uF, 16V, +/-10%, X5R, 0603; Manufacturer: MuRata; Polarized: N; CompType: Capacitor; U/M: EA; Cap_F: 0.00000047; Tolerance_%: 10; VDC_V: 16; TaMin_C: -55; TaMax_C: 85
C162 = C3225X5R1C226M: CAP, CERM, 22uF, 16V, +/-20%, X5R, 1210; Manufacturer: TDK; Cap_Case: 1210; ESR_Ohm: 0.002; IRMS_A: 3.5; Polarized: N; TaMax_C: 85; TaMin_C: -55; Tolerance_%: 20; VDC_V: 16; Cap_F: 0.000022; CompType: Capacitor; Value1: 0.002 ohm; U/M: EA; ValueDisplayed: 22µF
C163 = CC0805JRNP09BN471: CAP, CERM, 470pF, 50V, +/-5%, C0G/NP0, 0805; Manufacturer: Yageo America; Cap_Case: 0805; Polarized: N; TaMax_C: 125; TaMin_C: -55; Tolerance_%: 5; VDC_V: 50; Cap_F: 0.00000000047; CompType: Capacitor; U/M: EA
C166 C168 = GRM188R71E103KA01D: CAP, CERM, 0.01uF, 25V, +/-10%, X7R, 0603; Manufacturer: MuRata; Cap_Case: 0603; Polarized: N; TaMax_C: 125; TaMin_C: -55; Tolerance_%: 10; VDC_V: 25; Cap_F: 0.00000001; CompType: Capacitor; U/M: EA; ValueDisplayed: 0.01µF
C167 = 06035A102KAT2A: CAP, CERM, 1000pF, 50V, +/-10%, C0G/NP0, 0603; Manufacturer: AVX; Cap_Case: 0603; ESR_Ohm: 0.048; Polarized: N; TaMax_C: 125; TaMin_C: -55; Tolerance_%: 10; VDC_V: 50; Cap_F: 0.000000001; CompType: Capacitor; Value1: 0.048 ohm; U/M: EA
C169 = 06035A331JAT2A: CAP, CERM, 330pF, 50V, +/-5%, C0G/NP0, 0603; Manufacturer: AVX; Cap_Case: 0603; ESR_Ohm: 0.071; Polarized: N; TaMax_C: 125; TaMin_C: -55; Tolerance_%: 5; VDC_V: 50; Cap_F: 0.00000000033; CompType: Capacitor; Value1: 0.071 ohm; U/M: EA
C170 = GRM188R71H392KA01D: CAP, CERM, 3900pF, 50V, +/-10%, X7R, 0603; Manufacturer: MuRata; Cap_Case: 0603; Polarized: N; TaMax_C: 125; TaMin_C: -55; Tolerance_%: 10; VDC_V: 50; Cap_F: 0.0000000039; CompType: Capacitor; U/M: EA
D1 D8 = MBRS230LT3G: DIODE 2A 30V SMB; Manufacturer: ON Semiconductor; CompType: Zener; SymbolCreator: CSXHSC
D3 = 3SMBJ5936B-TP: Diode, Zener, 30V, 3W, SMB; Manufacturer: Micro Commercial Components; U/M: EA; Power_W: 3; Vz: 30; RJA_CperW: 226
D10 D45 D51 = MMSZ4702-V: Diode, Zener, 15V, 500mW, SOD-123; Manufacturer: Vishay-Semiconductor; U/M: EA; Power_W: 0.5; Vz: 15; Value1: 0.5W; RJA_CperW: 67
D11 D25 D27 D50 = 1N4148W-7-F: Diode, Ultrafast, 100V, 0.15A, SOD-123; Manufacturer: Diodes Inc.; U/M: EA; Vf_V: 1.25; Io_A: 0.15; Vr_V: 100; TJmax_C: 150; Value: 1.25V
D21 D64 = BAT54WS-7-F: Diode, Schottky, 30V, 0.2A, SOD-323; Manufacturer: Diodes Inc.; Vf_V: 0.7; Io_A: 0.2; Vr_V: 30; TJMax_C: 125; Value: 0.7V; U/M: EA
D23 D26 D28 = B180-13-F: Diode, Schottky, 80V, 1A, SMA; Manufacturer: Diodes Inc.; RJC_CperW: 25; Vf_V: 0.79; Io_A: 1; Vr_V: 80; TJMax_C: 150; Value: 0.79V; U/M: EA
F17 = 0437002.WR: FUSE 2A 63V  FAST ACTING; Manufacturer: LittleFuse Inc; SymbolVersion: use current date i.e. 2008-05-20; SymbolCreator: Use LDAP id
L3 L4 L6 L8 L9 = Ferrite Bead: Ferrite bead, 120mOhm, 2A, 0603; Manufacturer: Steward
L10 = CDRH6D28NP-100NC: Inductor, Shielded Drum Core, Ferrite, 10uH, 1.7A, 0.065 ohm, SMD; Manufacturer: Sumida; Ind_H: 10.0E-6; Imax_A: 1.7; Irms: 1.7A @ 30C rise; Isat: 1.7A @ 35% inductance drop; DCR_ohm: 0.065; U/M: EA; Expr1028: Digi-Key; Expr1029: 308-1487-1-ND
L11 = CDRH6D28NP-5R0NC: Inductor, Shielded Drum Core, Ferrite, 5uH, 2.4A, 0.031 ohm, SMD; Manufacturer: Sumida; Ind_H: 5.0E-6; Imax_A: 2.4; Irms: 2.4A @ 30C rise; Isat: 2.4A @ 35% inductance drop; DCR_ohm: 0.031; U/M: EA; Expr1028: Digi-Key; Expr1029: 308-1498-1-ND
Q12 Q44 = SI2337DS-T1-E3: MOSFET P-CH 80V 2.2A SOT23-3; Manufacturer: Vishay/Siliconix; ChType: P; Vgs_V: +/- 20V; IdsMax_A: 2.2
Q13 Q24 Q35 Q38 = 2N7002W-7-F: MOSFET N-CH 60V 115MA SOT323; Manufacturer: Vishay-Siliconix; ChType: N; VdsMax_V: 60; Value1: 1.8 ohm; Rdson45_Ohm: 1.8; Value2: 0.4 nC; QgTyp_nC: 0.4; Vgs_V: 20; IdsMax_A: 0.24
Q36 = SI7898DP-E3: MOSFET, N-CH, 150V, 3A, PowerPAK SO-8; Manufacturer: Vishay-Siliconix; ChType: N; VdsMax_V: 150; Value1: 0.076 ohm; Rdson45_Ohm: 0.076; Value2: 17 nC; QgTyp_nC: 17; Vgs_V: 20; IdsMax_A: 3; U/M: EA
Q37 = SI2323DS: MOSFET, P-CH, -20V, -3.7A, SOT-23; Manufacturer: Vishay-Siliconix; ChType: P; VdsMax_V: -20; Value1: 0.031 ohm; Rdson45_Ohm: 0.031; Value2: 12.5 nC; QgTyp_nC: 12.5; Vgs_V: -8; IdsMax_A: -3.7; U/M: EA
Q43 = BSS123W-7-F: MOSFET, N-CH, 100V, 0.17A, SOT-323; Manufacturer: Diodes Inc.; U/M: EA; ChType: N; VdsMax_V: 100; Value1: 10 ohm; Rdson45_Ohm: 10; Value2: ? nC; Vgs_V: 20; IdsMax_A: 0.17
R37 R93 R145 = CRCW0603200KJNEA: RES, 200k ohm, 5%, 0.1W, 0603; Manufacturer: Vishay-Dale; CompType: Resistor; Tolerance_%: 5; VDC_V: 75; Power_W: 0.1; Res_Ohm: 200000; EIA_Code: E24; TempCo: 200 ppm/C; U/M: EA
R44 = CRCW060347K0JNEA: RES, 47k ohm, 5%, 0.1W, 0603; Manufacturer: Vishay-Dale; CompType: Resistor; Tolerance_%: 5; VDC_V: 75; Power_W: 0.1; Res_Ohm: 47000; Value_Code: 47k0; EIA_Code: E24; TempCo: 200 ppm/C; U/M: EA
R58 = CRCW060349R9FKEA: RES, 49.9 ohm, 1%, 0.1W, 0603; Manufacturer: Vishay-Dale; CompType: Resistor; Tolerance_%: 1; VDC_V: 75; Power_W: 0.1; Value_Code: 49R9; EIA_Code: E96; TempCo: 100 ppm/C; U/M: EA
R63 = CRCW060310R0FKEA: RES, 10.0 ohm, 1%, 0.1W, 0603; Manufacturer: Vishay-Dale; CompType: Resistor; Tolerance_%: 1; VDC_V: 75; Power_W: 0.1; Res_ohm: 10; Value_Code: 10R0; EIA_Code: E96; U/M: EA; TempCo: 100 ppm/C
R64 R215 = CRCW060349k9FKEA: RES, 49.9k ohm, 1%, 0.1W, 0603; Manufacturer: Vishay-Dale; CompType: Resistor; Tolerance_%: 1; VDC_V: 75; Power_W: 0.1; Res_Ohm: 49900; Value_Code: 49k9; EIA_Code: E96; TempCo: 100 ppm/C; U/M: EA
R83 = CRCW0603249KFKEA: RES, 249k ohm, 1%, 0.1W, 0603; Manufacturer: Vishay-Dale; CompType: Resistor; Tolerance_%: 1; VDC_V: 75; Power_W: 0.1; Res_ohm: 249000; EIA_Code: E96; U/M: EA; TempCo: 100 ppm/C
R94 R98 R216 R244 R250 = RT0603DRE07100KL: 0.5%, 0.1W; Manufacturer: Yageo America; CompType: Resistor; Tolerance_%: 0.5; VDC_V: 75; Power_W: 0.1; Res_Ohm: 100000; EIA_Code: E192
R96 = CRCW0603316KFKEA: RES, 316k ohm, 1%, 0.1W, 0603; Manufacturer: Vishay-Dale; CompType: Resistor; Tolerance_%: 1; VDC_V: 75; Power_W: 0.1; Res_Ohm: 316000; EIA_Code: E96; TempCo: 100 ppm/C; U/M: EA
R138 = CRCW060354K9FKEA: RES, 54.9k ohm, 1%, 0.1W, 0603; Manufacturer: Vishay-Dale; CompType: Resistor; Tolerance_%: 1; VDC_V: 75; Power_W: 0.1; Res_ohm: 54900; Value_Code: 54k9; EIA_Code: E96; U/M: EA; TempCo: 100 ppm/C
R148 R176 = CRCW0603442KFKEA: RES, 442k ohm, 1%, 0.1W, 0603; Manufacturer: Vishay-Dale; CompType: Resistor; Tolerance_%: 1; VDC_V: 75; Power_W: 0.1; Res_ohm: 442000; EIA_Code: E96; U/M: EA; TempCo: 100 ppm/C
R150 = CRCW0603174KFKEA: RES, 174k ohm, 1%, 0.1W, 0603; Manufacturer: Vishay-Dale; CompType: Resistor; Res_ohm: 174000; Tolerance_%: 1; Power_W: 0.1; VDC_V: 75; TempCo: 100 ppm/C; EIA_Code: E96; U/M: EA
R152 = CRCW060326K7FKEA: RES, 26.7k ohm, 1%, 0.1W, 0603; Manufacturer: Vishay-Dale; CompType: Resistor; Tolerance_%: 1; VDC_V: 75; Power_W: 0.1; Res_ohm: 26700; Value_Code: 26k7; EIA_Code: E96; U/M: EA; TempCo: 100 ppm/C
R153 R187 = CRCW06035K90FKEA: RES, 5.90k ohm, 1%, 0.1W, 0603; Manufacturer: Vishay-Dale; CompType: Resistor; Tolerance_%: 1; VDC_V: 75; Power_W: 0.1; Res_ohm: 5900; Value_Code: 5k90; EIA_Code: E96; U/M: EA; TempCo: 100 ppm/C
R210 = CRCW0603910KJNEA: RES, 910k ohm, 5%, 0.1W, 0603; Manufacturer: Vishay-Dale; CompType: Resistor; Tolerance_%: 5; VDC_V: 75; Power_W: 0.1; Res_ohm: 910000; EIA_Code: E24; U/M: EA; TempCo: 200 ppm/C
R211 = CRCW0603150KJNEA: RES, 150k ohm, 5%, 0.1W, 0603; Manufacturer: Vishay-Dale; CompType: Resistor; Tolerance_%: 5; VDC_V: 75; Power_W: 0.1; Res_ohm: 150000; EIA_Code: E24; U/M: EA; TempCo: 200 ppm/C
R212 = CRCW1206100RFKEA: RES, 100 ohm, 1%, 0.25W, 1206; Manufacturer: Vishay-Dale; CompType: Resistor; Tolerance_%: 1; VDC_V: 200; Power_W: 0.25; Value_Code: 100R; EIA_Code: E96; TempCo: 100 ppm/C; U/M: EA
R213 R218 = CRCW06030000Z0EA: as R48 on sheet BOTTOM_ACB_Converter
R214 R220 = CRCW08055K10JNEA: RES, 5.1k ohm, 5%, 0.125W, 0805; Manufacturer: Vishay-Dale; CompType: Resistor; Tolerance_%: 5; VDC_V: 150; Power_W: 0.125; Res_Ohm: 5100; Value_Code: 5k10; EIA_Code: E24; TempCo: 200 ppm/C; U/M: EA
R217 = CRCW120610R0FKEA: RES, 10.0 ohm, 1%, 0.25W, 1206; Manufacturer: Vishay-Dale; CompType: Resistor; Tolerance_%: 1; VDC_V: 200; Power_W: 0.25; Res_Ohm: 10; Value_Code: 10R0; EIA_Code: E96; TempCo: 100 ppm/C; U/M: EA
R219 = CRCW060310K0FKEA: RES, 10.0k ohm, 1%, 0.1W, 0603; Manufacturer: Vishay-Dale; CompType: Resistor; Res_ohm: 10000; Value_Code: 10k0; Tolerance_%: 1; Power_W: 0.1; VDC_V: 75; TempCo: 100 ppm/C; EIA_Code: E96; U/M: EA
R221 = CRCW0603100RFKEA: RES, 100 ohm, 1%, 0.1W, 0603; Manufacturer: Vishay-Dale; CompType: Resistor; Tolerance_%: 1; VDC_V: 75; Power_W: 0.1; Value_Code: 100R; EIA_Code: E96; TempCo: 100 ppm/C; U/M: EA
R222 = CRCW060375K0FKEA: RES, 75.0k ohm, 1%, 0.1W, 0603; Manufacturer: Vishay-Dale; CompType: Resistor; Tolerance_%: 1; VDC_V: 75; Power_W: 0.1; Res_ohm: 75000; Value_Code: 75k0; EIA_Code: E96; U/M: EA; TempCo: 100 ppm/C
R224 = MCR25JZHFLR270: RES, 0.27 ohm, 1%, 0.5W, 1210; Manufacturer: Rohm; CompType: Resistor; Tolerance_%: 1; VDC_V: 0; Power_W: 0.5; Value_Code: R270; EIA_Code: E96; TempCo: 200 ppm/C; U/M: EA
R226 = CRCW0603115KFKEA: RES, 115k ohm, 1%, 0.1W, 0603; Manufacturer: Vishay-Dale; CompType: Resistor; Tolerance_%: 1; VDC_V: 75; Power_W: 0.1; Res_Ohm: 115000; EIA_Code: E96; TempCo: 100 ppm/C; U/M: EA
R227 = CRCW060310K5FKEA: RES, 10.5k ohm, 1%, 0.1W, 0603; Manufacturer: Vishay-Dale; CompType: Resistor; Tolerance_%: 1; VDC_V: 75; Power_W: 0.1; Res_Ohm: 10500; Value_Code: 10k5; EIA_Code: E96; TempCo: 100 ppm/C; U/M: EA
R228 = CRCW06031K15FKEA: RES, 1.15k ohm, 1%, 0.1W, 0603; Manufacturer: Vishay-Dale; CompType: Resistor; Tolerance_%: 1; VDC_V: 75; Power_W: 0.1; Res_Ohm: 1150; Value_Code: 1k15; EIA_Code: E96; TempCo: 100 ppm/C; U/M: EA
R241 R242 = RT0603DRE07100KL: RES, 100k ohm, 0.5%, 0.1W, 0603; Manufacturer: Yageo America; CompType: Resistor; Tolerance_%: 0.5; VDC_V: 75; Power_W: 0.1; Res_Ohm: 100000; EIA_Code: E192; TempCo: 50 ppm/C; U/M: EA
R243 = CRCW060366K5FKEA: RES, 66.5k ohm, 1%, 0.1W, 0603; Manufacturer: Vishay-Dale; CompType: Resistor; Tolerance_%: 1; VDC_V: 75; Power_W: 0.1; Res_Ohm: 66500; Value_Code: 66k5; EIA_Code: E96; TempCo: 100 ppm/C; U/M: EA
R246 R249 = CRCW060310K0FKEA: RES, 10.0k ohm, 1%, 0.1W, 0603; Manufacturer: Vishay-Dale; CompType: Resistor; Tolerance_%: 1; VDC_V: 75; Power_W: 0.1; Res_Ohm: 10000; Value_Code: 10k0; EIA_Code: E96; TempCo: 100 ppm/C; U/M: EA
R251 = CRCW06031k00FKEA: as R247 on sheet BOTTOM_ACB_Converter
T1 = 749196111: Wurth 749196111 flyback transformer; Manufacturer: Wurth Elektronik; SymbolVersion: use current date i.e. 2008-05-20; SymbolCreator: Use LDAP id; CompType: Used in some BOM reports.  Useful for finding later.
U9 = EMB1466MM: Dual 150mA Ultra Low-Dropout Regulator; Manufacturer: National Semiconductor; CompType: LDO IC; PowerWise: N
U10 = TPS7A4001: VREG, LDO, ADJ, 50mA, MSOP8; Manufacturer: TI; SymbolCreator: CSXHSC; U/M: EA
U11 = LM26400YMH/NOPB: Dual 2A, 500kHz Wide Input Range Buck Regulator, 16-pin TSSOP-EP, Pb-Free; Manufacturer: National Semiconductor; PackageTopMarking: NSUZXYTT*L26400*YMH; PowerWise: N; CompType: Switcher
U13 = EMB1487MM: Low Noise Regulated Switched Capacitor Voltage Inverter; Manufacturer: National Semiconductor; CompType: Switch Caps; PowerWise: N
U33 U35 = EMB1437MP: 500 mA Low Dropout Regulator; Manufacturer: National Semiconductor; CompType: LDO IC; PowerWise: N
U34 = EMB1420MM: 100V Current Mode PWM Controller; Manufacturer: National Semiconductor; CompType: Switcher

## Sheet Cell Sensing.SchDoc: Cell Sensing (AFE)
size B; Date: Not shown in title block; ApprovedBy: Not shown in title block; CheckedBy: Not shown in title block; Author: Not shown in title block; CompanyName: Not shown in title block; DrawnBy: Not shown in title block; Engineer: Not shown in title block; Organization: Not shown in title block; Address1: Not shown in title block; Address2: Not shown in title block; Address3: Not shown in title block; Address4: Not shown in title block; DocumentNumber: 2; Revision: Use project parameter SCH_Rev; SheetNumber: 2; SheetTotal: 14; PageSetup: Record=PageOptions|CenterHorizontal=True|CenterVertical=True|PrintScale=1.09|XCorrection=1.00|YCorrection=1.00|PrintKind=0|BorderSize=5000000|LeftOffset=0|BottomOffset=0|Orientation=2|PaperLength=1000|PaperWidth=1000|Scale=100|PaperSource=15|PrintQuality=600|MediaType=1|DitherType=10|PaperKind=11x17|PrintScaleMode=1
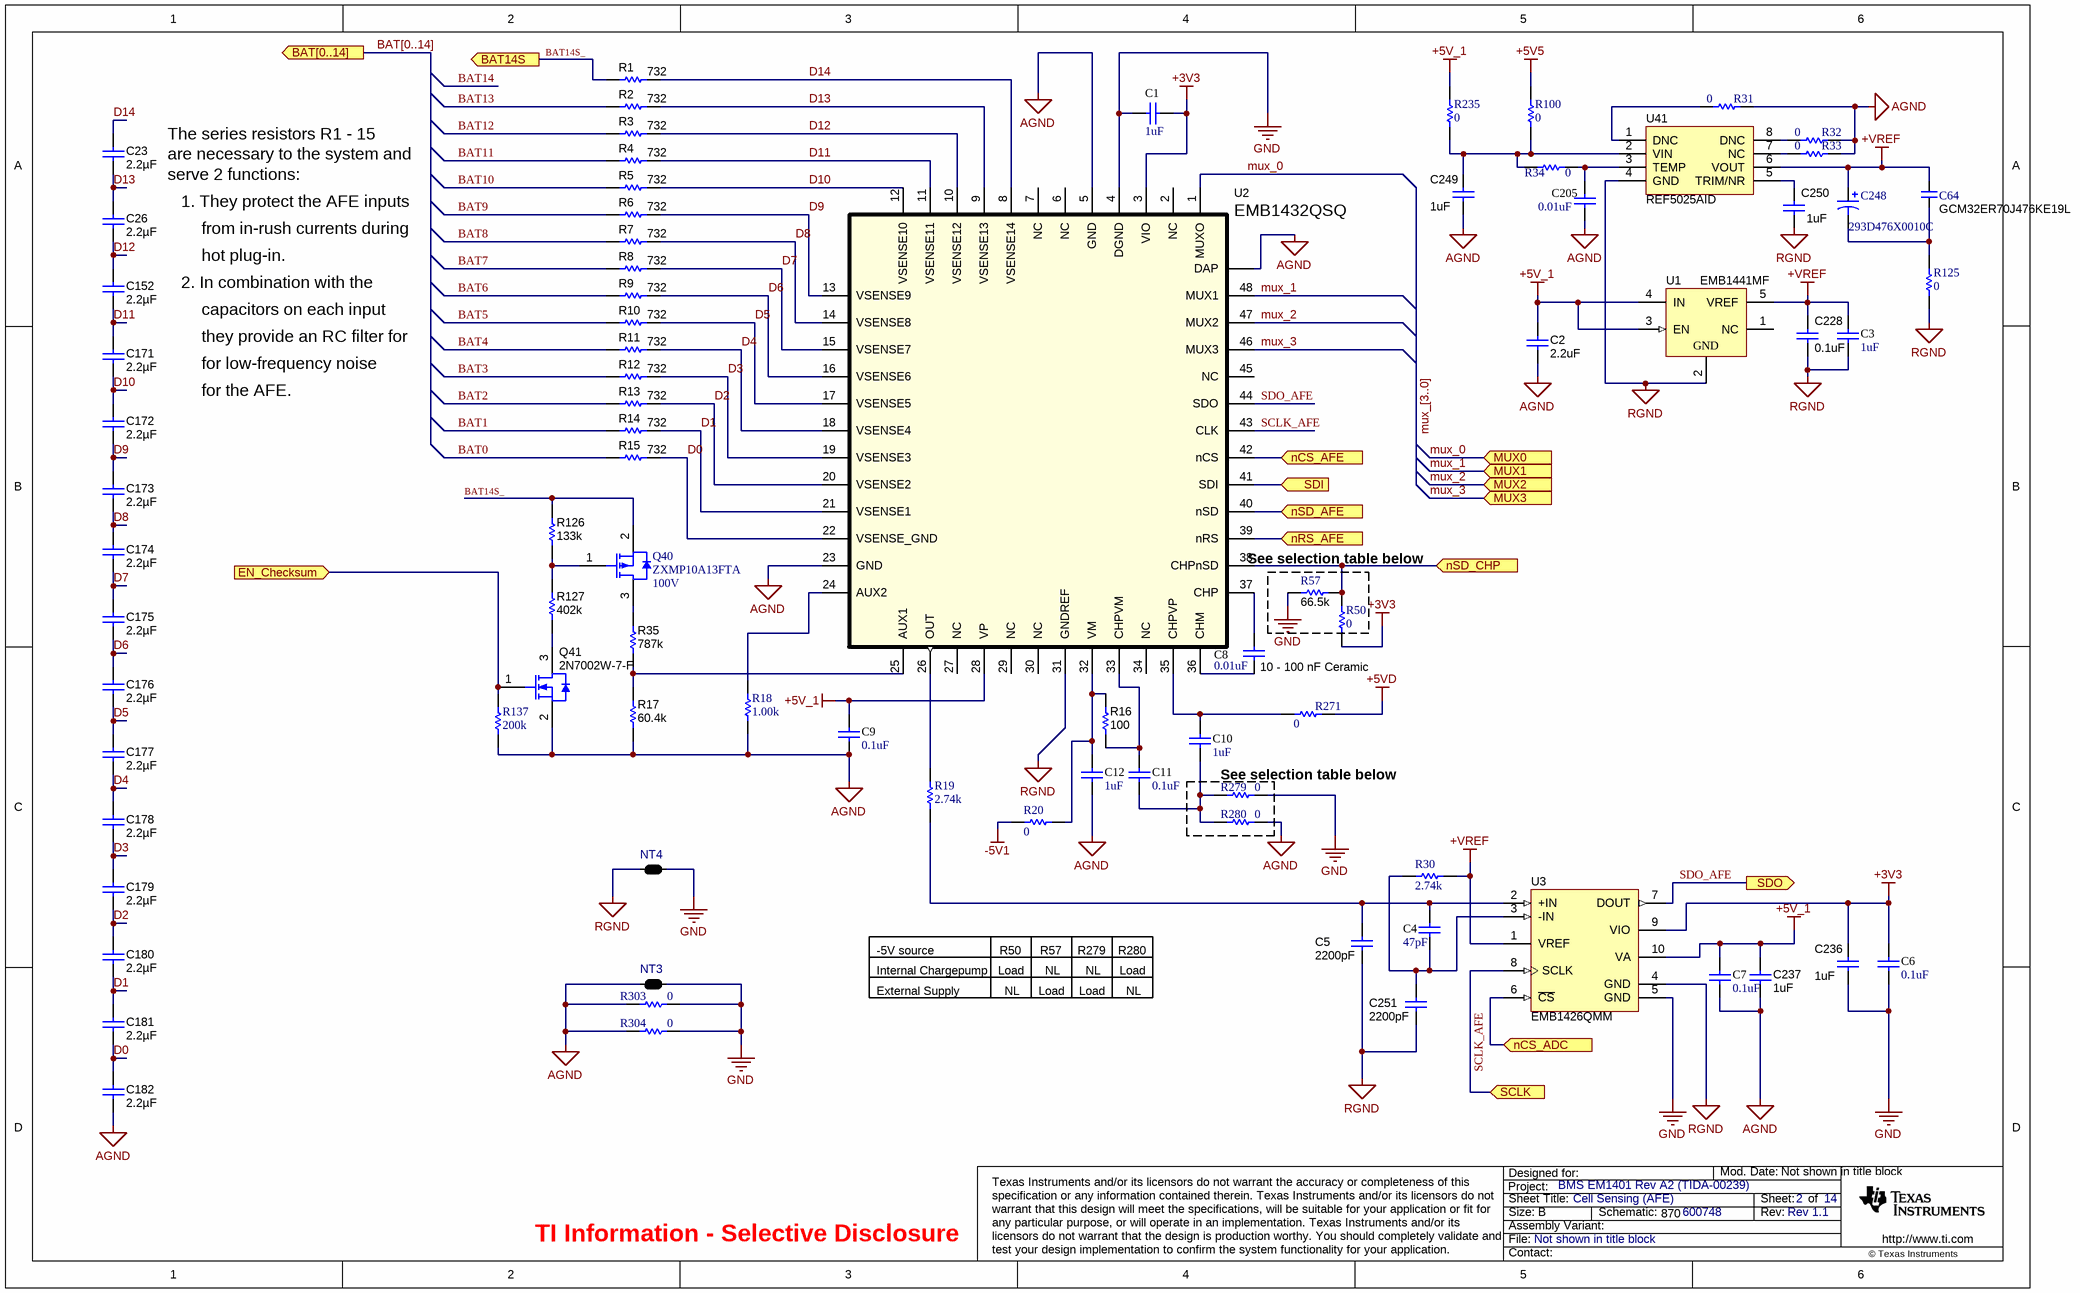
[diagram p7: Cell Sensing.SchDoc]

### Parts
C1  value 1uF  [0805_HV]  (hidden comment: C2012X7R1E105K)
C2  value 2.2uF  [0603L]  (hidden comment: GRM188R71A225KE15D)
C3  value 1uF  [0603L]  (hidden comment: C1608X5R1C105K)
C4  value 47pF  [0603L]  (hidden comment: GRM1885C1H470JA01D)
C5  value 2200pF  [0603L]  (hidden comment: C1608C0G1H222J)
C6  value 0.1uF  [0603L]  (hidden comment: C1608X7R1C104K)
C7  value 0.1uF  [0603L]  (hidden comment: C1608X7R1C104K)
C8  value 0.01uF  [0603L]  (hidden comment: C1608X7R1H103K)
C9  value 0.1uF  [0603L]  (hidden comment: C1608X7R1C104K)
C10  value 1uF  [0805_HV]  (hidden comment: C2012X7R1E105K)
C11  value 0.1uF  [0603L]  (hidden comment: C1608X7R1C104K)
C12  value 1uF  [0805_HV]  (hidden comment: C2012X7R1E105K)
C23  ValueDisplayed: 2.2µF  [0603L]  (hidden comment: C0603C225K9PACTU)
C26  ValueDisplayed: 2.2µF  [0603L]  (hidden comment: C0603C225K9PACTU)
C64  GCM32ER70J476KE19L  [1210]
C152  ValueDisplayed: 2.2µF  [0603L]  (hidden comment: C0603C225K9PACTU)
C171  ValueDisplayed: 2.2µF  [0603L]  (hidden comment: C0603C225K9PACTU)
C172  ValueDisplayed: 2.2µF  [0603L]  (hidden comment: C0603C225K9PACTU)
C173  ValueDisplayed: 2.2µF  [0603L]  (hidden comment: C0603C225K9PACTU)
C174  ValueDisplayed: 2.2µF  [0603L]  (hidden comment: C0603C225K9PACTU)
C175  ValueDisplayed: 2.2µF  [0603L]  (hidden comment: C0603C225K9PACTU)
C176  ValueDisplayed: 2.2µF  [0603L]  (hidden comment: C0603C225K9PACTU)
C177  ValueDisplayed: 2.2µF  [0603L]  (hidden comment: C0603C225K9PACTU)
C178  ValueDisplayed: 2.2µF  [0603L]  (hidden comment: C0603C225K9PACTU)
C179  ValueDisplayed: 2.2µF  [0603L]  (hidden comment: C0603C225K9PACTU)
C180  ValueDisplayed: 2.2µF  [0603L]  (hidden comment: C0603C225K9PACTU)
C181  ValueDisplayed: 2.2µF  [0603L]  (hidden comment: C0603C225K9PACTU)
C182  ValueDisplayed: 2.2µF  [0603L]  (hidden comment: C0603C225K9PACTU)
C205  value 0.01uF  [0603L]  (hidden comment: GRM188R71E103KA01D)
C228  value 0.1uF  [0603L]  (hidden comment: C0603C104K8RACTU)
C236  value 1uF  [0603L]  (hidden comment: C1608X7R1C105K)
C237  value 1uF  [0603L]  (hidden comment: C1608X7R1C105K)
C248  293D476X0010C  [6032-28]
C249  value 1uF  [0603L]  (hidden comment: C1608X7R1C105K)
C250  value 1uF  [0603L]  (hidden comment: C1608X7R1C105K)
C251  value 2200pF  [0603L]  (hidden comment: C1608C0G1H222J)
NT3  (no value)  [0805_Net_Tie]  (net tie, no BOM)
NT4  (no value)  [0805_Net_Tie]  (net tie, no BOM)
Q40  ZXMP10A13FTA  value 100V  [MF03A_N]
Q41  2N7002W-7-F  [SOT-323]
R1  value 732  [0603L]  (hidden comment: CRCW0603732RFKEA)
R2  value 732  [0603L]  (hidden comment: CRCW0603732RFKEA)
R3  value 732  [0603L]  (hidden comment: CRCW0603732RFKEA)
R4  value 732  [0603L]  (hidden comment: CRCW0603732RFKEA)
R5  value 732  [0603L]  (hidden comment: CRCW0603732RFKEA)
R6  value 732  [0603L]  (hidden comment: CRCW0603732RFKEA)
R7  value 732  [0603L]  (hidden comment: CRCW0603732RFKEA)
R8  value 732  [0603L]  (hidden comment: CRCW0603732RFKEA)
R9  value 732  [0603L]  (hidden comment: CRCW0603732RFKEA)
R10  value 732  [0603L]  (hidden comment: CRCW0603732RFKEA)
R11  value 732  [0603L]  (hidden comment: CRCW0603732RFKEA)
R12  value 732  [0603L]  (hidden comment: CRCW0603732RFKEA)
R13  value 732  [0603L]  (hidden comment: CRCW0603732RFKEA)
R14  value 732  [0603L]  (hidden comment: CRCW0603732RFKEA)
R15  value 732  [0603L]  (hidden comment: CRCW0603732RFKEA)
R16  value 100  [0603L]  (hidden comment: CRCW0603100RFKEA)
R17  value 60.4k  [0603L]  (hidden comment: CRCW060360K4FKEA)
R18  value 1.00k  [0603L]  (hidden comment: CRCW06031K00FKEA)
R19  value 2.74k  [0603L]  (hidden comment: CRCW06032K74FKEA)
R20  value 0  [0603L]  (hidden comment: CRCW06030000Z0EA)
R30  value 2.74k  [0603L]  (hidden comment: CRCW06032K74FKEA)
R31  value 0  [0603L]  (hidden comment: CRCW06030000Z0EA)
R32  value 0  [0603L]  (hidden comment: CRCW06030000Z0EA)
R33  value 0  [0603L]  (hidden comment: CRCW06030000Z0EA)
R34  value 0  [0603L]  (hidden comment: CRCW06030000Z0EA)
R35  value 787k  [0603L]  (hidden comment: CRCW0603787KFKEA)
R50  value 0  [0603L]  (hidden comment: CRCW06030000Z0EA)
R57  value 66.5k  [0603L]  (hidden comment: CRCW060366K5FKEA)
R100  value 0  [0603L]  (hidden comment: CRCW06030000Z0EA)
R125  value 0  [0603L]  (hidden comment: CRCW06030000Z0EA)
R126  value 133k  [0603L]  (hidden comment: CRCW0603133KFKEA)
R127  value 402k  [0603L]  (hidden comment: CRCW0603402KFKEA)
R137  value 200k  [0603L]  (hidden comment: CRCW0603200KJNEA)
R235  value 0  [0603L]  (hidden comment: CRCW06030000Z0EA)
R271  value 0  [0603L]  (hidden comment: CRCW06030000Z0EA)
R279  value 0  [0603L]  (hidden comment: CRCW06030000Z0EA)
R280  value 0  [0603L]  (hidden comment: CRCW06030000Z0EA)
R303  value 0  [0603L]  (hidden comment: CRCW06030000Z0EA)
R304  value 0  [0603L]  (hidden comment: CRCW06030000Z0EA)
U1  EMB1441MF  [MF05A_L]
U2  EMB1432QSQ  [SQA48B]
U3  EMB1426QMM  [MUB10A_N]
U41  REF5025AID  [M08A_L]

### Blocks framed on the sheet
See selection table below: R279 R280

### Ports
BAT14S, BAT[0..14], EN_Checksum (in), MUX0 (in), MUX1 (in), MUX2 (in), MUX3 (in), nCS_ADC (in), nCS_AFE (in), nRS_AFE (in), nSD_AFE (in), nSD_CHP (in), SCLK (in), SDI (in), SDO (out)

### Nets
+3V3: C1.2 C6.1 C236.1 R50.1 U2.3(VIO) U3.9(VIO)
+5V5: R100.1
+5V_1: C2.1 C7.1 C9.1 C237.1 R235.2 U1.3(EN) U1.4(IN) U2.28(VP) U3.10(VA)
+5VD: R271.2
+VREF: C3.1 C64.2 C228.1 C248.1(+) R30.1 U1.5(VREF) U3.1(VREF) U41.6(VOUT)
-5V1: R20.1
AGND: C2.2 C7.2 C9.2 C12.2 C182.2 C205.2 C237.2 C249.2 NT3.1 Q41.2(S) R17.1 R18.1 R31.2 R32.2 R33.2 R137.1 R280.2 R303.1 R304.1 U2.5(GND) U2.23(GND) U2.49(DAP)
BAT0: C1.1 C6.2 C236.2 NT3.2 NT4.2 R15.1 R57.2 R279.2 R303.2 R304.2 U2.4(DGND) U3.5(GND)  [also labelled GND]
RGND: C3.2 C5.2 C228.2 C250.1 C251.2 NT4.1 R125.2 U1.2(GND) U2.31(GNDREF) U3.4(GND) U41.4(GND)
BAT1: R14.1
BAT2: R13.1
BAT3: R12.1
BAT4: R11.1
BAT5: R10.1
BAT6: R9.1
BAT7: R8.1
BAT8: R7.1
BAT9: R6.1
BAT10: R5.1
BAT11: R4.1
BAT12: R3.1
BAT13: R2.1
BAT14S_: Q40.2(S) R1.1 R126.2 ; port BAT14S
D0: C181.2 C182.1 R15.2 U2.22(VSENSE_GND)
D1: C180.2 C181.1 R14.2 U2.21(VSENSE1)
D2: C179.2 C180.1 R13.2 U2.20(VSENSE2)
D3: C178.2 C179.1 R12.2 U2.19(VSENSE3)
D4: C177.2 C178.1 R11.2 U2.18(VSENSE4)
D5: C176.2 C177.1 R10.2 U2.17(VSENSE5)
D6: C175.2 C176.1 R9.2 U2.16(VSENSE6)
D7: C174.2 C175.1 R8.2 U2.15(VSENSE7)
D8: C173.2 C174.1 R7.2 U2.14(VSENSE8)
D9: C172.2 C173.1 R6.2 U2.13(VSENSE9)
D10: C171.2 C172.1 R5.2 U2.12(VSENSE10)
D11: C152.2 C171.1 R4.2 U2.11(VSENSE11)
D12: C26.2 C152.1 R3.2 U2.10(VSENSE12)
D13: C23.2 C26.1 R2.2 U2.9(VSENSE13)
D14: C23.1 R1.2 U2.8(VSENSE14)
EN_Checksum_: Q41.1(G) R137.2 ; port EN_Checksum
MOSI_1_: U2.41(SDI) ; port SDI
mux_0: U2.1(MUXO) ; port MUX0  [project net AFE_MUX0_]
mux_1: U2.48(MUX1) ; port MUX1  [project net AFE_MUX1_]
mux_2: U2.47(MUX2) ; port MUX2  [project net AFE_MUX2_]
mux_3: U2.46(MUX3) ; port MUX3  [project net AFE_MUX3_]
nCS_ADC_: U3.6(~{CS}) ; port nCS_ADC
nCS_AFE_: U2.42(nCS) ; port nCS_AFE
nRS_AFE_: U2.39(nRS) ; port nRS_AFE
nSD_AFE_: U2.40(nSD) ; port nSD_AFE
nSD_AFE_CHP_: R50.2 R57.1 U2.38(CHPnSD) ; port nSD_CHP
SCLK_AFE: U2.43(CLK) U3.8(SCLK) ; port SCLK  [project net SCLK_ADC_]
SDO_AFE: U2.44(SDO) U3.7(DOUT) ; port SDO  [project net SDO_ADC_]
NetC4_1: C4.1 C5.1 R19.1 U3.2(+IN)
NetC4_2: C4.2 C251.1 R30.2 U3.3(-IN)
NetC8_1: C8.1 U2.37(CHP)
NetC8_2: C8.2 U2.36(CHM)
NetC10_1: C10.1 R271.1 U2.35(CHPVP)
NetC10_2: C10.2 C11.2 R279.1 R280.1
NetC11_1: C11.1 R16.1 U2.33(CHPVM)
NetC12_1: C12.1 R16.2 R20.2 U2.32(VM)
NetC64_1: C64.1 C248.2(-) R125.1
NetC205_1: C205.1 R34.1 U41.3(TEMP)
NetC249_1: C249.1 R34.2 R100.2 R235.1 U41.2(VIN)
NetC250_2: C250.2 U41.5(TRIM/NR)
NetQ40_1: Q40.1(G) R126.1 R127.2
NetQ40_3: Q40.3(D) R35.2
NetQ41_3: Q41.3(D) R127.1
NetR17_2: R17.2 R35.1 U2.25(AUX1)
NetR18_2: R18.2 U2.24(AUX2)
NetR19_2: R19.2 U2.26(OUT)
NetR31_1: R31.1 U41.1(DNC)
NetR32_1: R32.1 U41.8(DNC)
NetR33_1: R33.1 U41.7(NC)

Not connected (* = marked no-connect by the designer): U1 1(NC); U2 2(NC) 6(NC) 7(NC) 27(NC) 29(NC) 30(NC) 34(NC) 45(NC)

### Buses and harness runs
bus BAT[0..14] = port BAT[0..14]
bus mux_[3..0]

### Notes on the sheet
- The series resistors R1 - 15
- are necessary to the system and
- serve 2 functions:
- 1. They protect the AFE inputs
- from in-rush currents during
- 2. In combination with the
- hot plug-in.
- capacitors on each input
- they provide an RC filter for
- for low-frequency noise
- for the AFE.
- See selection table below
- (near C8) 10 - 100 nF Ceramic
- -5V source
- Internal Chargepump
- Load
- R50
- NL
- R57
- R279
- R280
- External Supply
- TI Information - Selective Disclosure

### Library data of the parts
C1 C10 C12 = C2012X7R1E105K: as C35 on sheet VR
C2 = GRM188R71A225KE15D: CAP, CERM, 2.2uF, 10V, +/-10%, X7R, 0603; Manufacturer: MuRata; Cap_Case: 0603; ESR_Ohm: 0.009; Polarized: N; TaMax_C: 125; TaMin_C: -55; Tolerance_%: 10; Cap_F: 0.0000022; CompType: Capacitor; Value1: 0.009 ohm; U/M: EA; ValueDisplayed: 2.2µF
C3 = C1608X5R1C105K: CAP, CERM, 1uF, 16V, +/-10%, X5R, 0603; Manufacturer: TDK; Cap_Case: 0603; ESR_Ohm: 0.0057; Polarized: N; TaMax_C: 85; TaMin_C: -55; Tolerance_%: 10; VDC_V: 16; Cap_F: 0.000001; CompType: Capacitor; Value1: 0.0057 ohm; U/M: EA; ValueDisplayed: 1µF
C4 = GRM1885C1H470JA01D: CAP, CERM, 47pF, 50V, +/-5%, C0G/NP0, 0603; Manufacturer: MuRata; Cap_Case: 0603; Polarized: N; TaMax_C: 125; TaMin_C: -55; Tolerance_%: 5; VDC_V: 50; Cap_F: 0.000000000047; CompType: Capacitor; U/M: EA
C5 C251 = C1608C0G1H222J: CAP, CERM, 2200pF, 50V, +/-5%, C0G/NP0, 0603; Manufacturer: TDK; Cap_Case: 0603; ESR_Ohm: 0.0375; Polarized: N; TaMax_C: 125; TaMin_C: -55; Tolerance_%: 5; VDC_V: 50; Cap_F: 0.0000000022; CompType: Capacitor; Value1: 0.0375 ohm; U/M: EA
C6 C7 C9 C11 = C1608X7R1C104K: as C121 on sheet BOTTOM_ACB_Converter
C8 = C1608X7R1H103K: CAP, CERM, 0.01uF, 50V, +/-10%, X7R, 0603; Manufacturer: TDK; Cap_Case: 0603; ESR_Ohm: 0.0539; Polarized: N; TaMax_C: 125; TaMin_C: -55; Tolerance_%: 10; VDC_V: 50; Cap_F: 0.00000001; CompType: Capacitor; Value1: 0.0539 ohm; U/M: EA; ValueDisplayed: 0.01µF
C23 C26 C152 C171-C182 = C0603C225K9PACTU: CAP, CERM, 2.2uF, 6.3V, +/-10%, X5R, 0603; Manufacturer: Kemet; Cap_Case: 0603; Polarized: N; TaMax_C: 85; TaMin_C: -55; Tolerance_%: 10; VDC_V: 6.3; Cap_F: 0.0000022; CompType: Capacitor; U/M: EA
C64 = GCM32ER70J476KE19L: CAP CER 47UF 6.3V X7R 1210; Manufacturer: Murata; CompType: Capacitor X7R
C205 = GRM188R71E103KA01D: as C166 on sheet VR
C228 = C0603C104K8RACTU: CAP, CERM, 0.1uF, 10V, +/-10%, X7R, 0603; Manufacturer: Kemet; Cap_Case: 0603; Polarized: N; TaMax_C: 125; TaMin_C: -55; Tolerance_%: 10; Cap_F: 0.0000001; CompType: Capacitor; U/M: EA; ValueDisplayed: 0.1µF
C236 C237 C249 C250 = C1608X7R1C105K: as C105 on sheet VR
C248 = 293D476X0010C: CAP TANT 47UF 10V 20% SMD; Manufacturer: Vishay/Sprague; CompType: Capacitor Tant.
NT3 NT4 = NetTie: Value1: DNP
Q40 = ZXMP10A13FTA: MOSFET P-CH 100V 700MA SOT23-3; Manufacturer: Diodes/Zetex; ChType: P; Vgs_V: +/- 20V; IdsMax_A: -3.1
Q41 = 2N7002W-7-F: as Q13 on sheet VR
R1-R15 = CRCW0603732RFKEA: RES, 732 ohm, 1%, 0.1W, 0603; Manufacturer: Vishay-Dale; CompType: Resistor; Tolerance_%: 1; VDC_V: 75; Power_W: 0.1; Value_Code: 732R; EIA_Code: E96; U/M: EA; TempCo: 100 ppm/C
R16 = CRCW0603100RFKEA: as R221 on sheet VR
R17 = CRCW060360K4FKEA: RES, 60.4k ohm, 1%, 0.1W, 0603; Manufacturer: Vishay-Dale; CompType: Resistor; Tolerance_%: 1; VDC_V: 75; Power_W: 0.1; Res_ohm: 60400; Value_Code: 60k4; EIA_Code: E96; U/M: EA; TempCo: 100 ppm/C
R18 = CRCW06031K00FKEA: RES, 1.00k ohm, 1%, 0.1W, 0603; Manufacturer: Vishay-Dale; CompType: Resistor; Tolerance_%: 1; VDC_V: 75; Power_W: 0.1; Res_Ohm: 1000; Value_Code: 1k00; EIA_Code: E96; TempCo: 100 ppm/C; U/M: EA
R19 R30 = CRCW06032K74FKEA: RES, 2.74k ohm, 1%, 0.1W, 0603; Manufacturer: Vishay-Dale; CompType: Resistor; Tolerance_%: 1; VDC_V: 75; Power_W: 0.1; Res_Ohm: 2740; Value_Code: 2k74; EIA_Code: E96; TempCo: 100 ppm/C; U/M: EA
R20 R31-R34 R50 R100 R125 R235 R271 R279 R280 R303 R304 = CRCW06030000Z0EA: as R48 on sheet BOTTOM_ACB_Converter
R35 = CRCW0603787KFKEA: RES, 787k ohm, 1%, 0.1W, 0603; Manufacturer: Vishay-Dale; CompType: Resistor; Tolerance_%: 1; VDC_V: 75; Power_W: 0.1; Res_ohm: 787000; EIA_Code: E96; U/M: EA; TempCo: 100 ppm/C
R57 = CRCW060366K5FKEA: as R243 on sheet VR
R126 = CRCW0603133KFKEA: RES, 133k ohm, 1%, 0.1W, 0603; Manufacturer: Vishay-Dale; CompType: Resistor; Tolerance_%: 1; VDC_V: 75; Power_W: 0.1; Res_ohm: 133000; EIA_Code: E96; U/M: EA; TempCo: 100 ppm/C
R127 = CRCW0603402KFKEA: RES, 402k ohm, 1%, 0.1W, 0603; Manufacturer: Vishay-Dale; CompType: Resistor; Tolerance_%: 1; VDC_V: 75; Power_W: 0.1; Res_ohm: 402000; EIA_Code: E96; U/M: EA; TempCo: 100 ppm/C
R137 = CRCW0603200KJNEA: as R37 on sheet VR
U1 = EMB1441MF: SOT-23 Precision Low Dropout Voltage Reference; Manufacturer: National Semiconductor; CompType: Voltage Reference IC; PowerWise: Y
U2 = EMB1432QSQ: 14 channel AFE; Manufacturer: National Semiconductor; CompType: Used in BOM report; SymbolCreator: cwiosc
U3 = EMB1426QMM: 14-Bit, 50 kSPS to 250 kSPS, Differential Input, Micro Power A/D Converter; Manufacturer: National Semiconductor; CompType: ADC IC; PowerWise: Y
U41 = REF5025AID: IC PREC VREF 2.5V SOIC8; Manufacturer: Texas Instruments; SymbolVersion: use current date i.e. 2008-05-20; SymbolCreator: Use LDAP id; CompType: Voltage Reference; Description: TEXAS INSTRUMENTS - REF5025AIDG4 - IC, SM, VOLT REF, 2.5V; Reference Voltage: 2.5; Dielectric: 3; No. of Pins: 8; Case Style: SOIC; Min Temperature Operating: -40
